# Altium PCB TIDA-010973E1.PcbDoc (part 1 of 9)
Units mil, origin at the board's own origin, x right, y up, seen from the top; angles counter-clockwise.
Board outline 5166 x 3669 mil, 8 copper layers (L01 - TOP, L02 - GND, L03 - SIG, L04 - GND, L05 - PWR, L06 - SIG, L07 - GND, L08 - BOTTOM), stack 61.7 mil thick; 677 components, 493 nets, 2522 pads, 1424 vias.
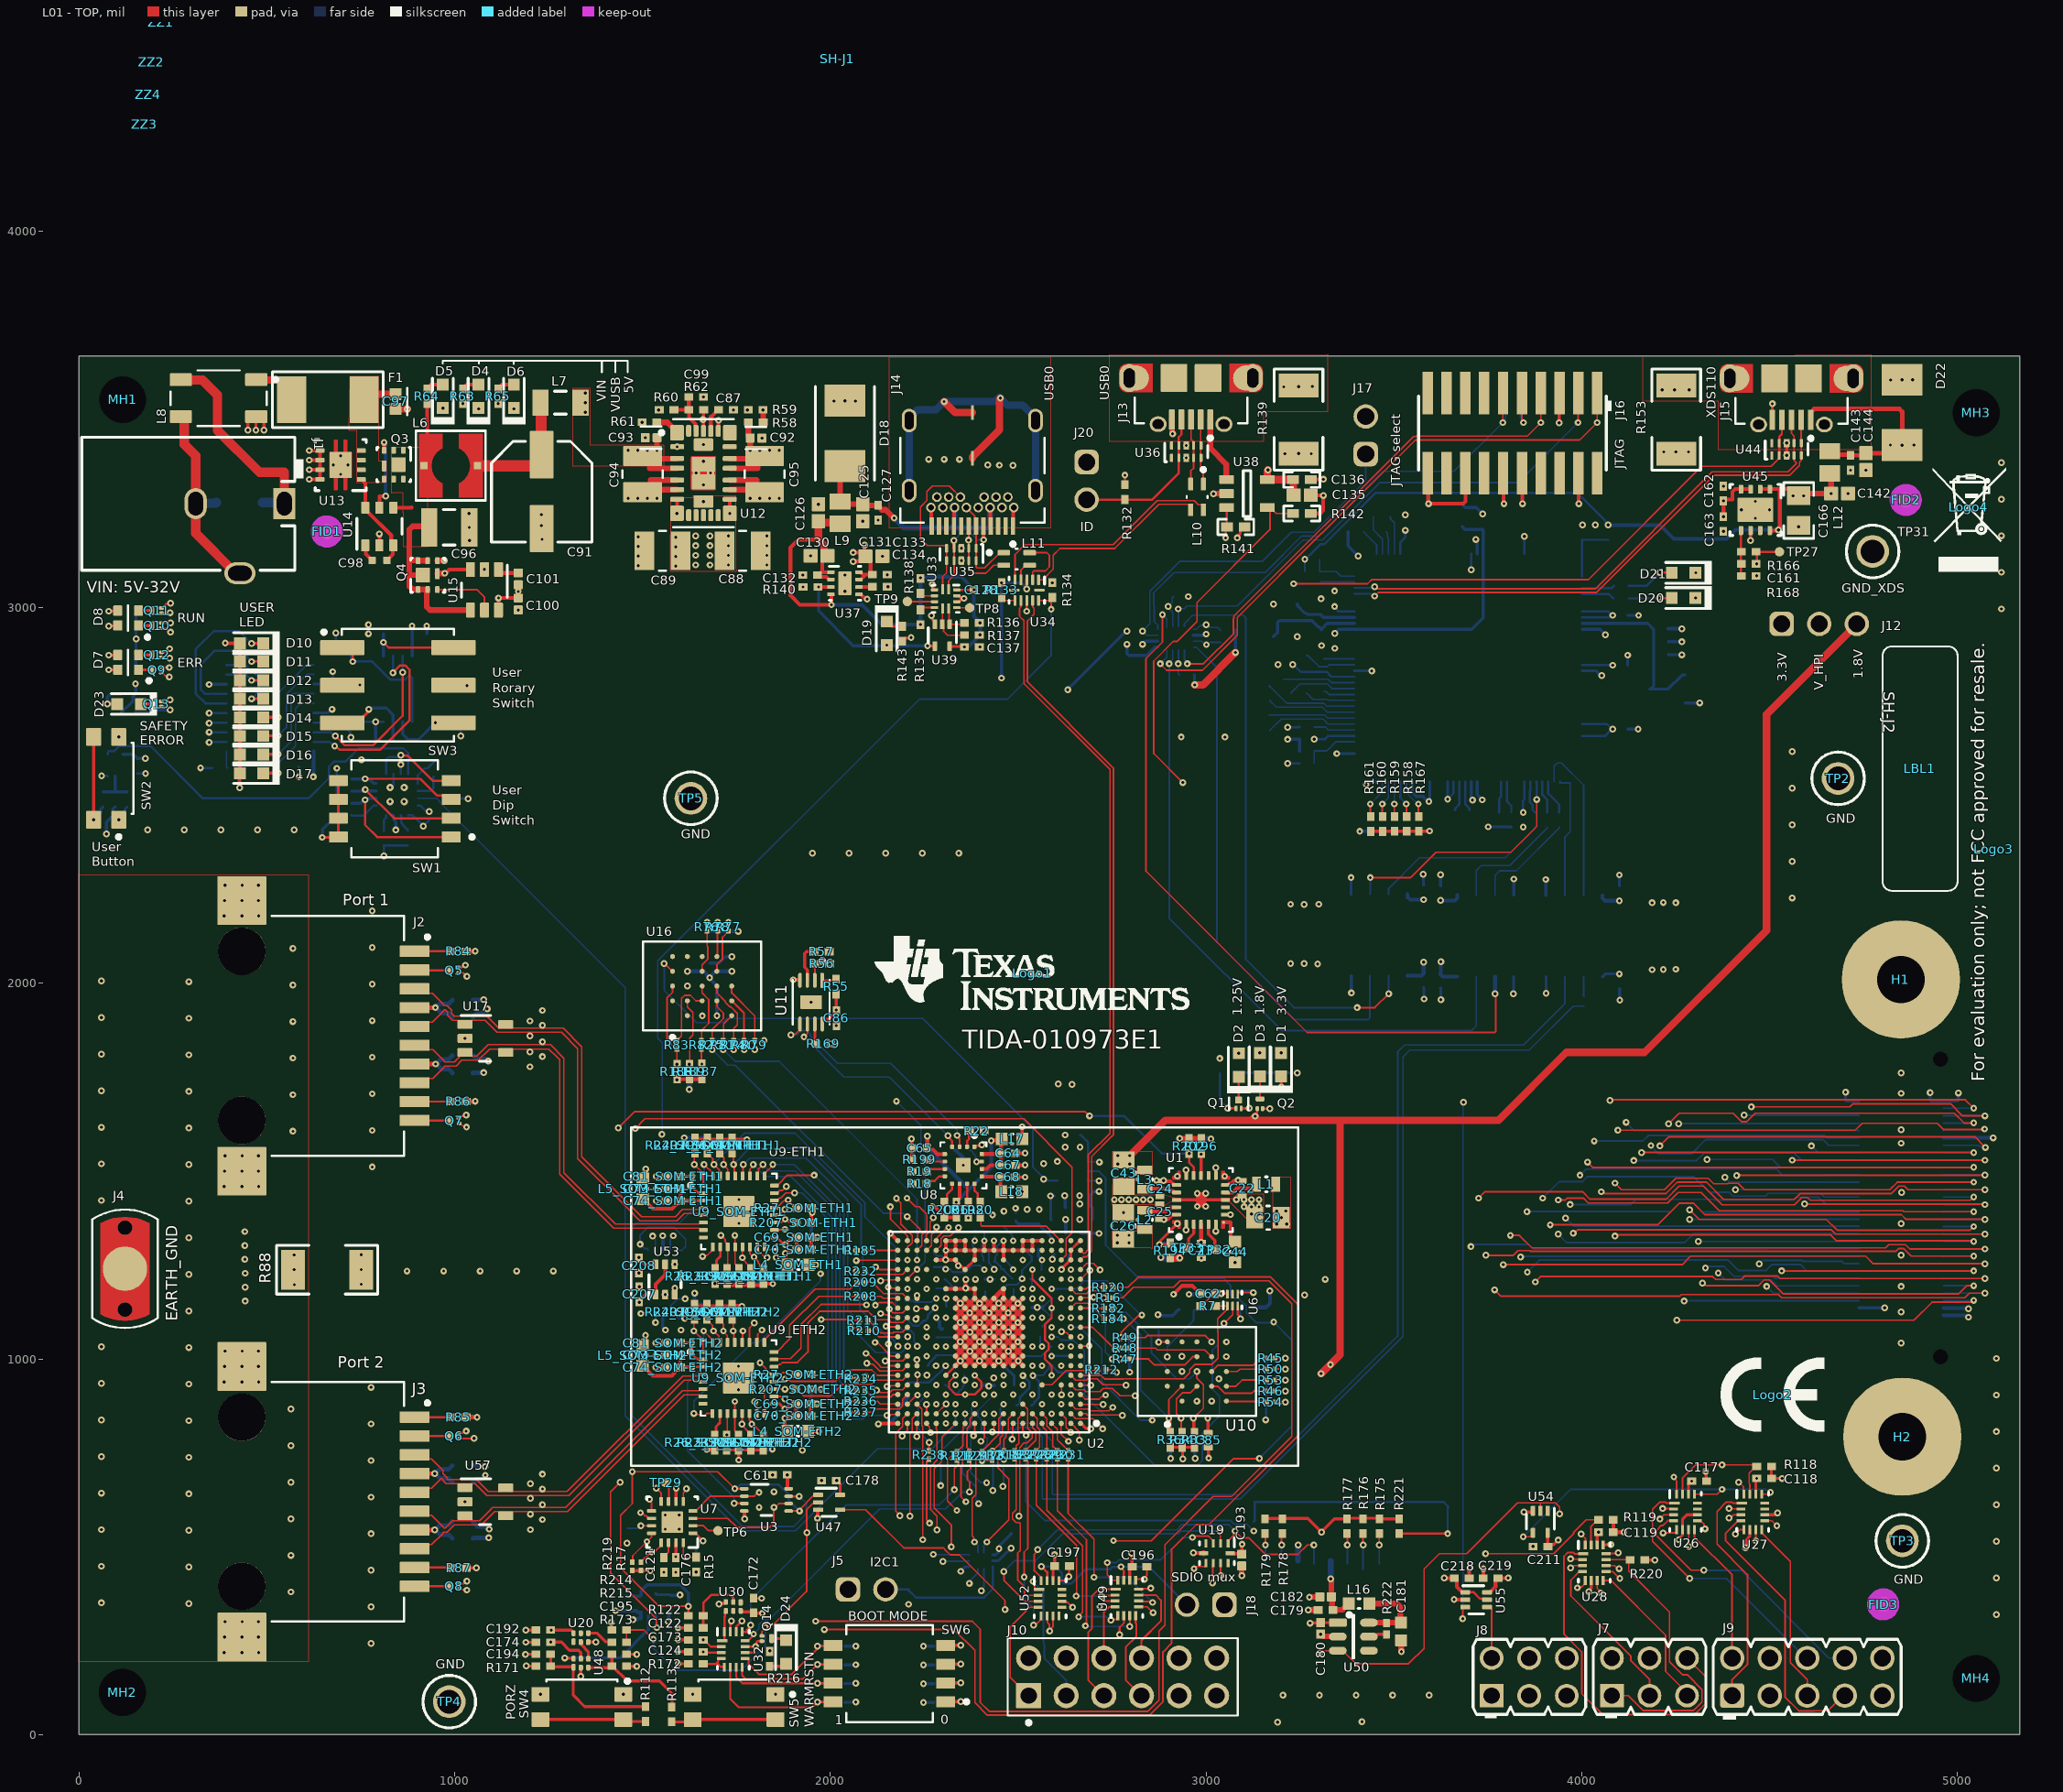
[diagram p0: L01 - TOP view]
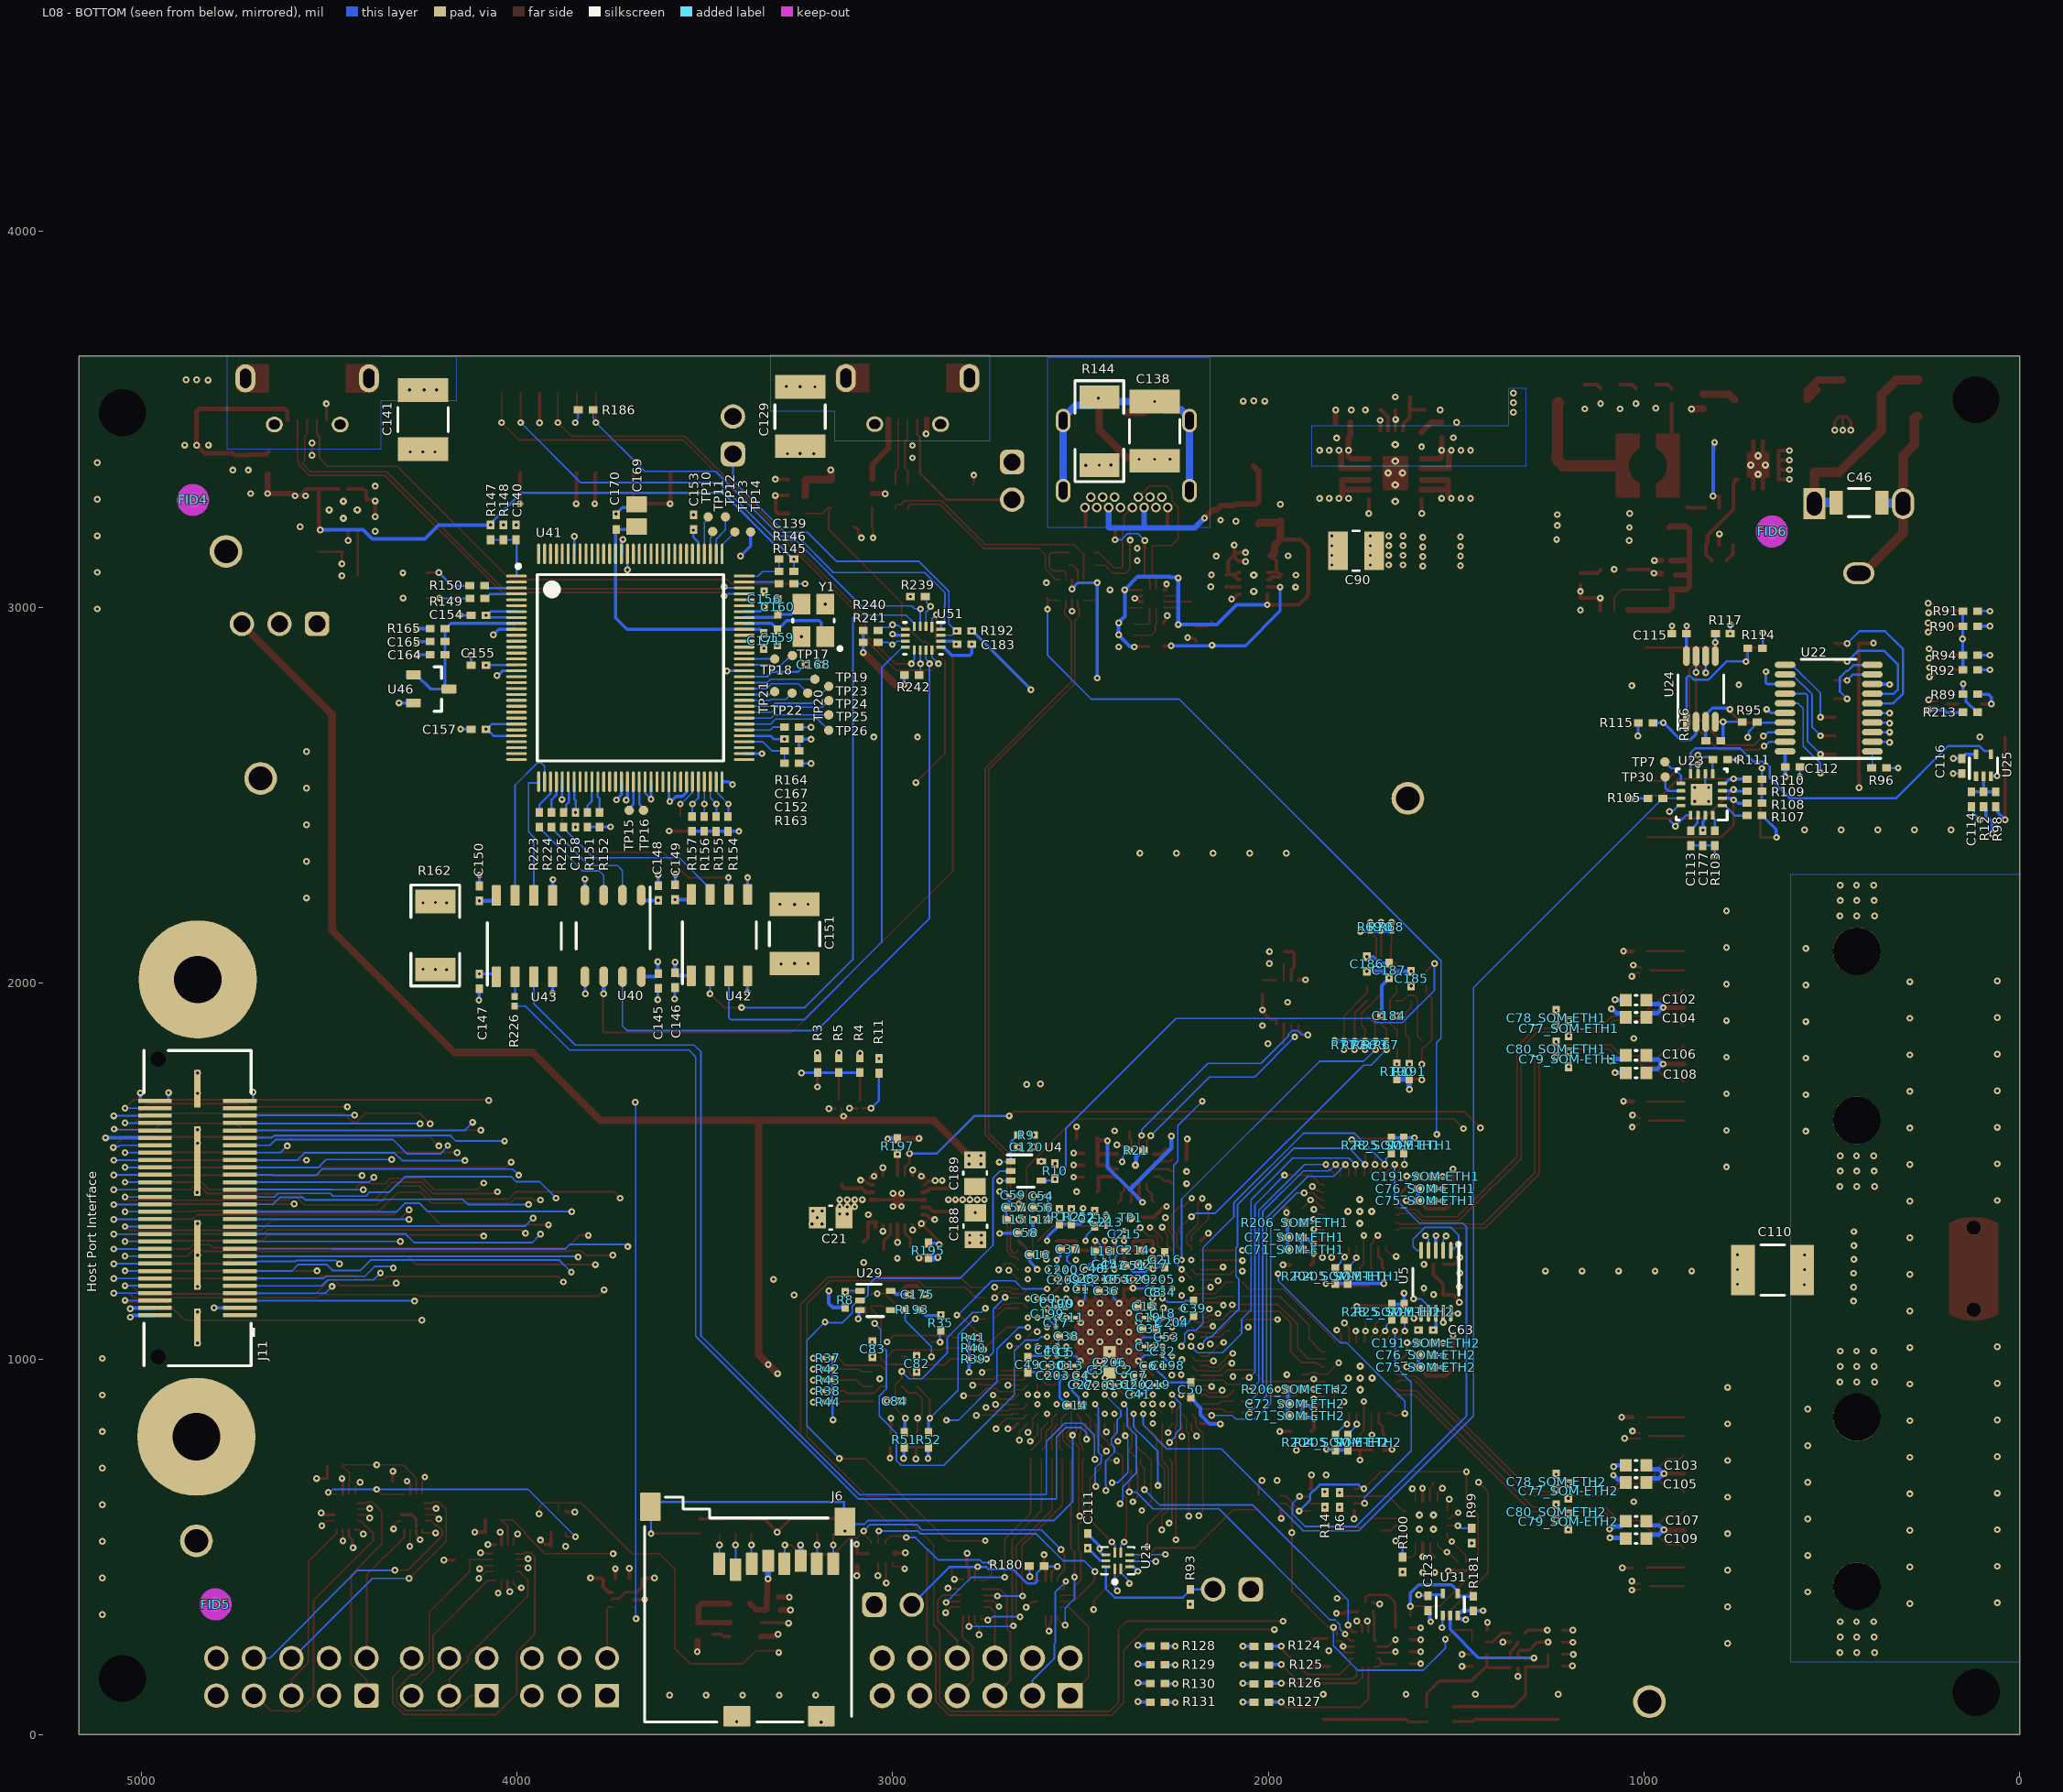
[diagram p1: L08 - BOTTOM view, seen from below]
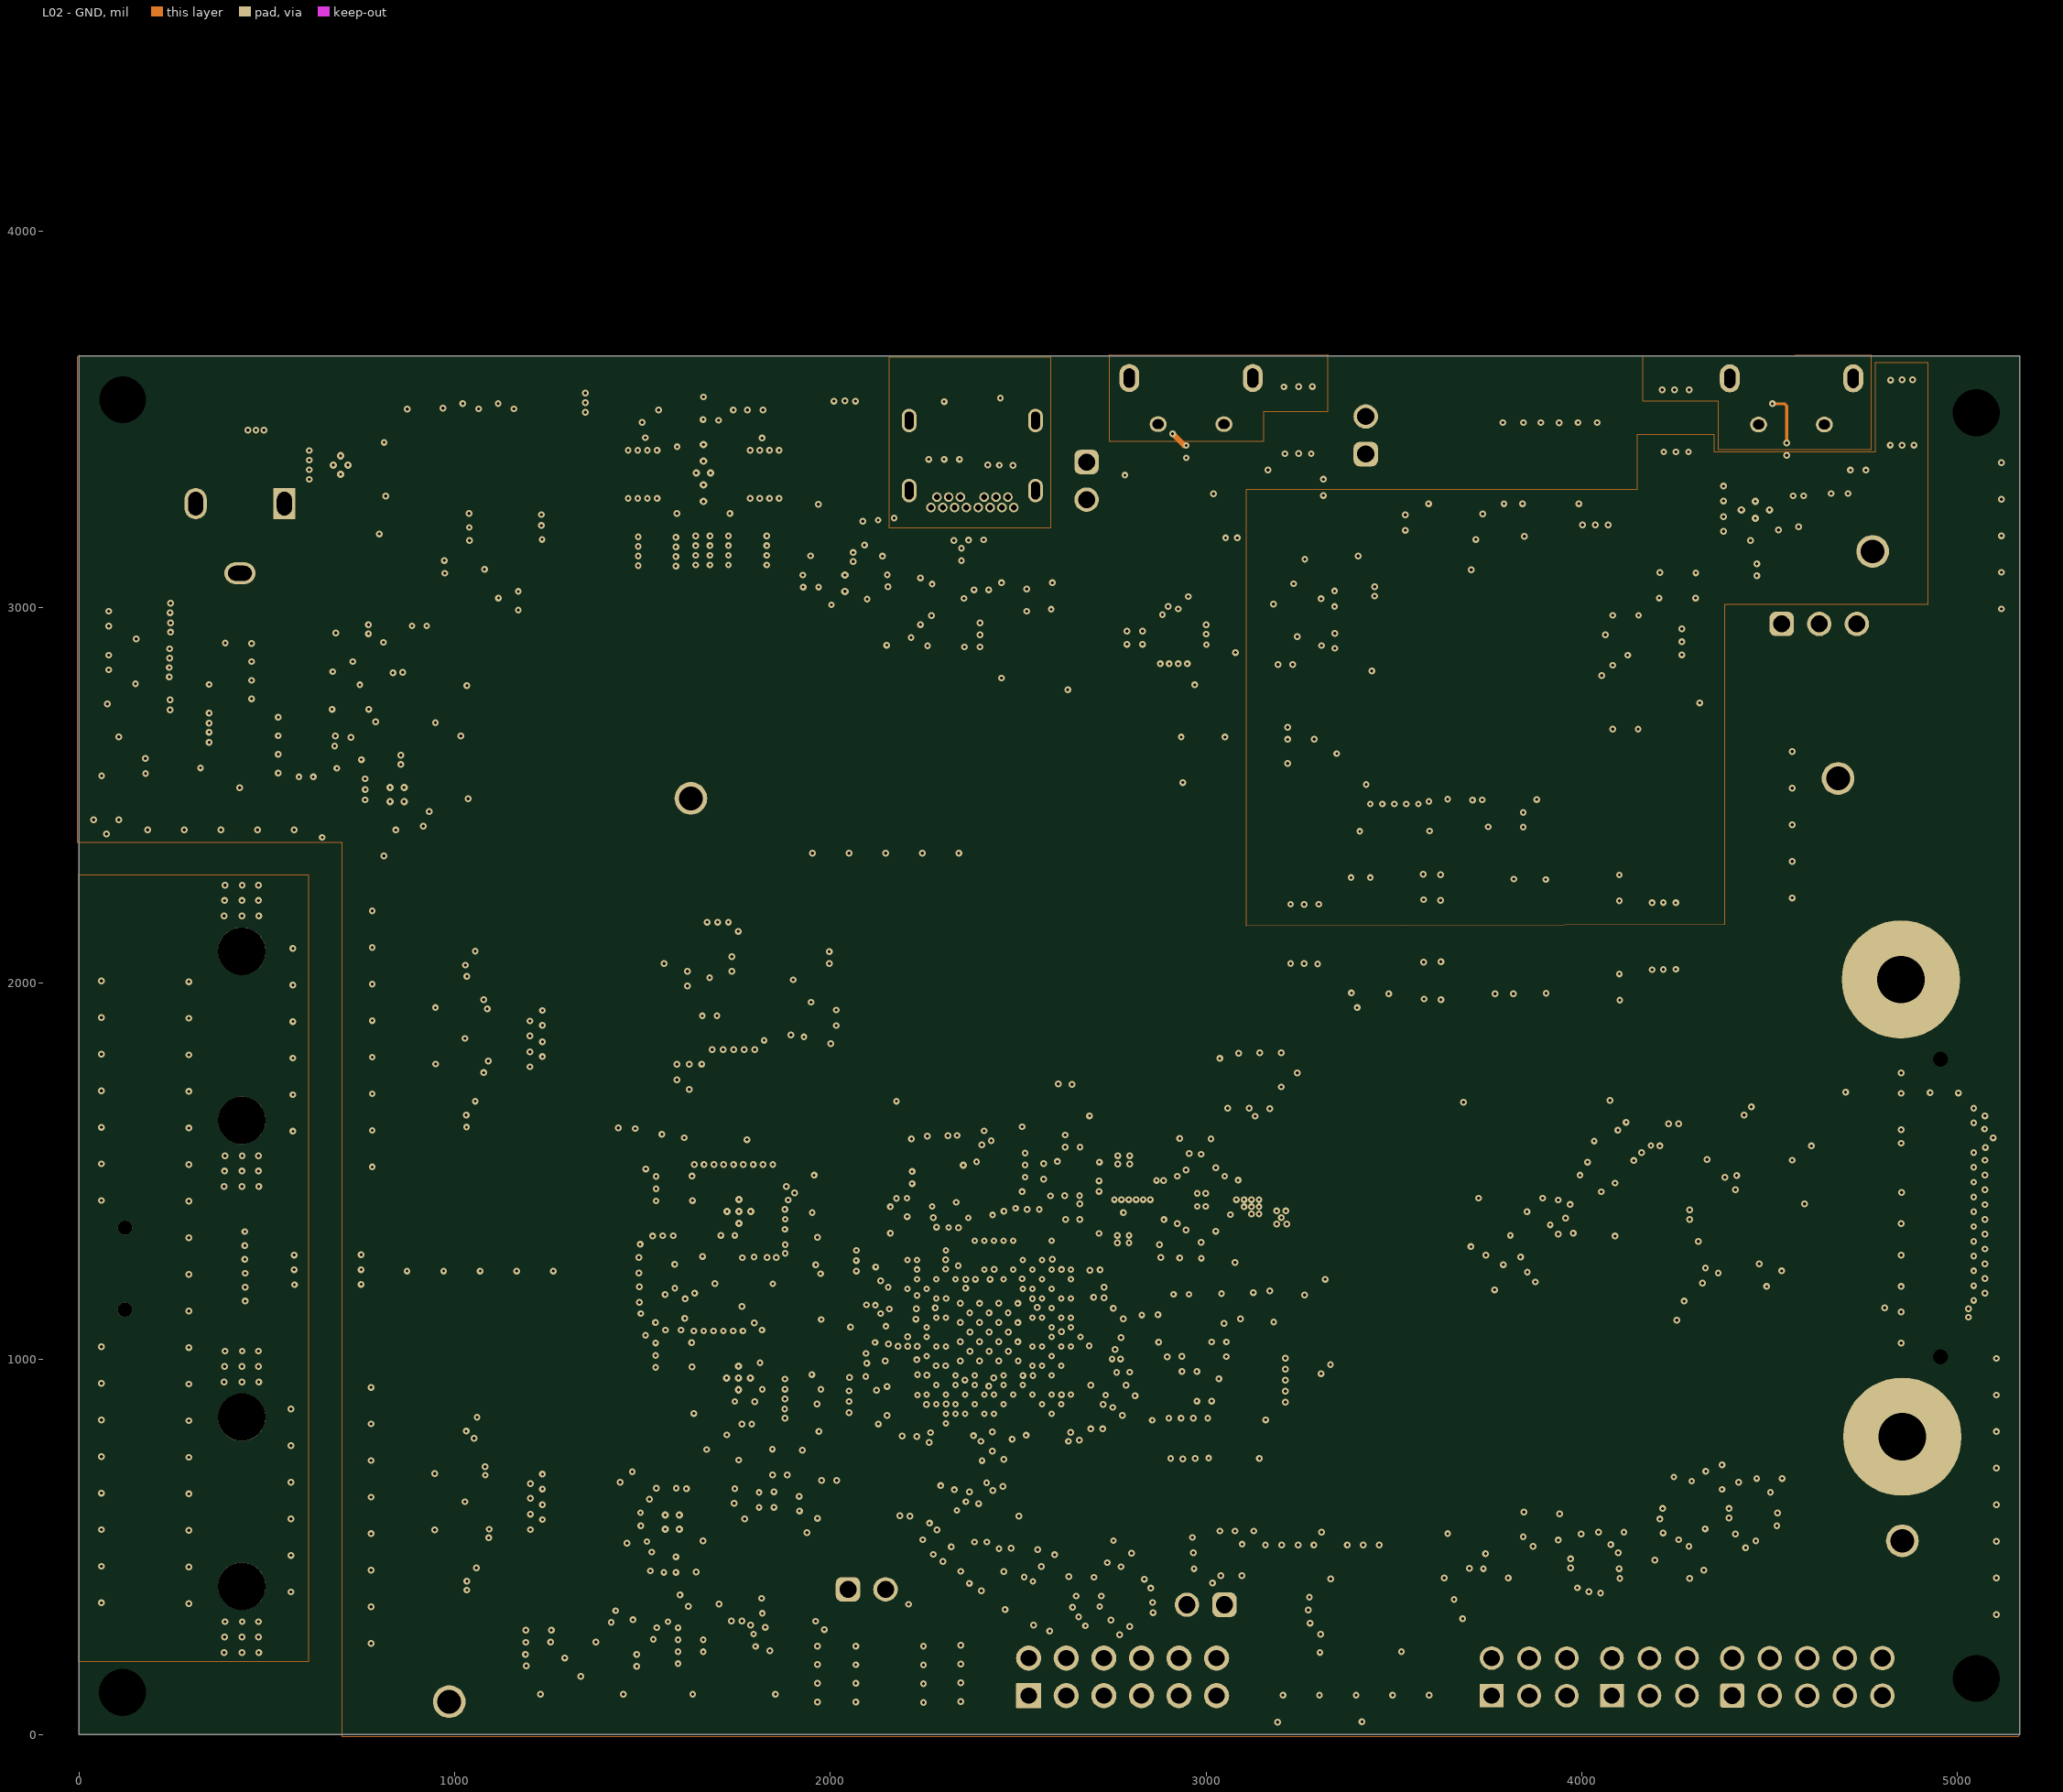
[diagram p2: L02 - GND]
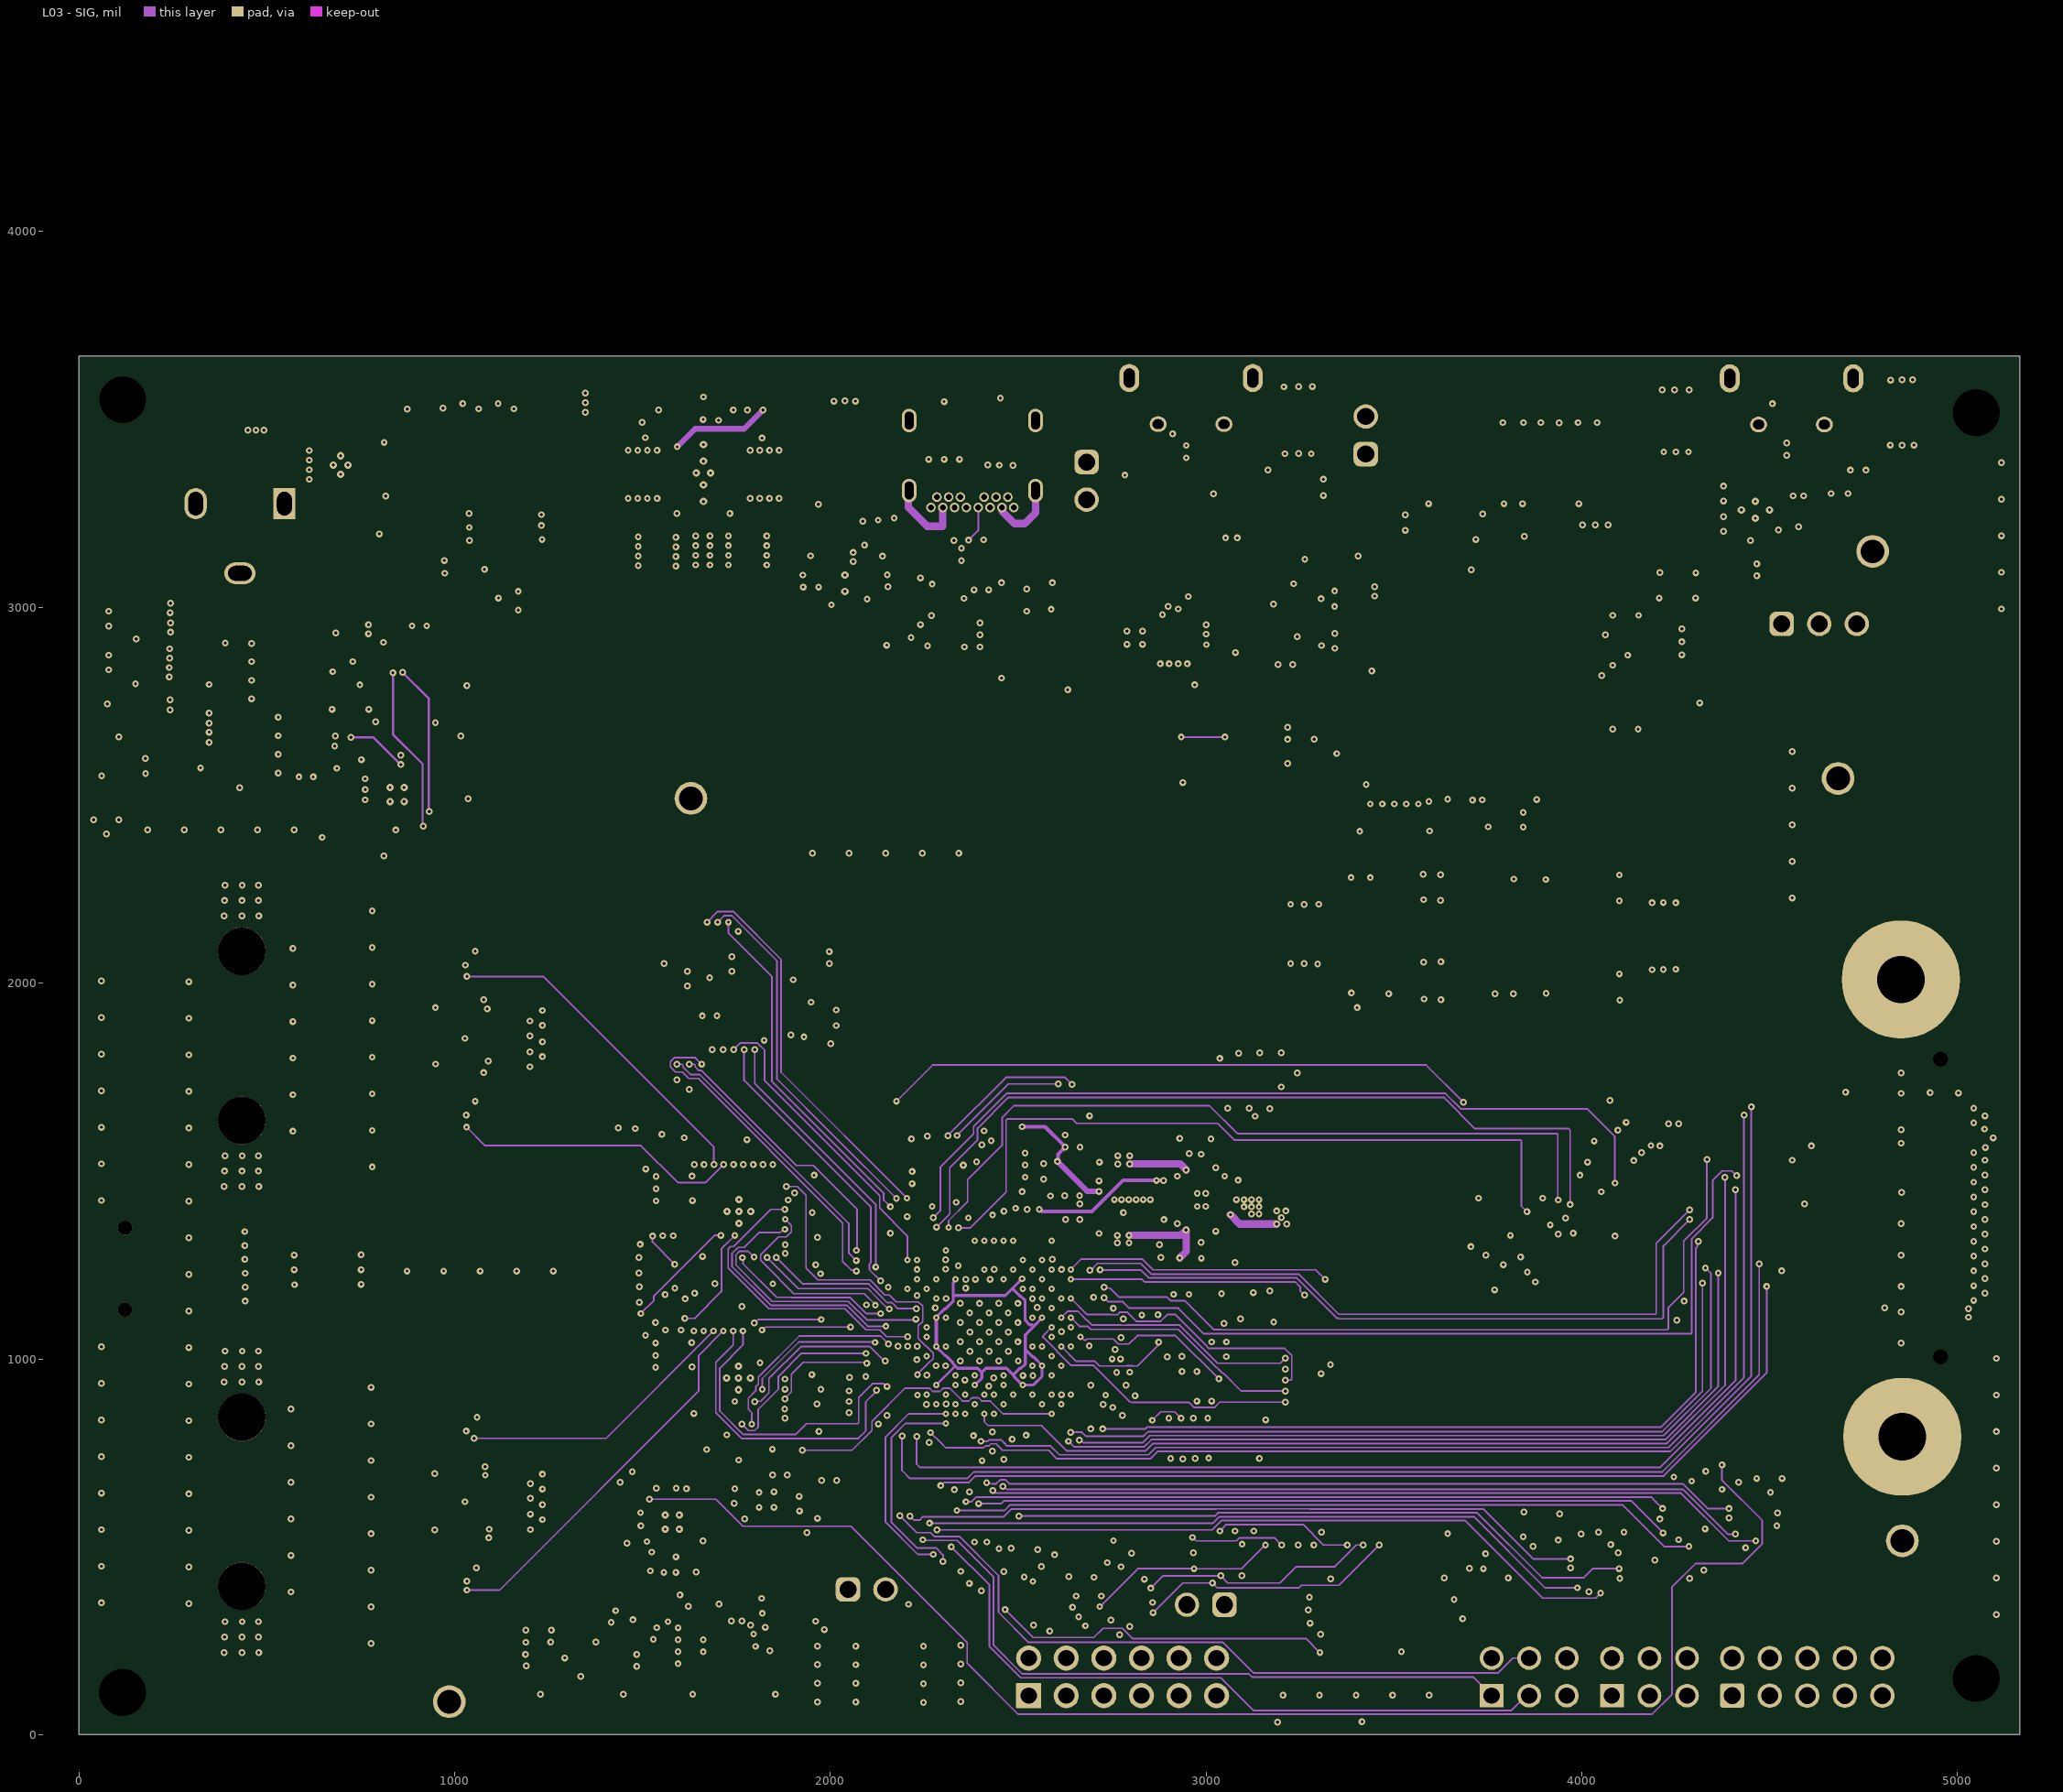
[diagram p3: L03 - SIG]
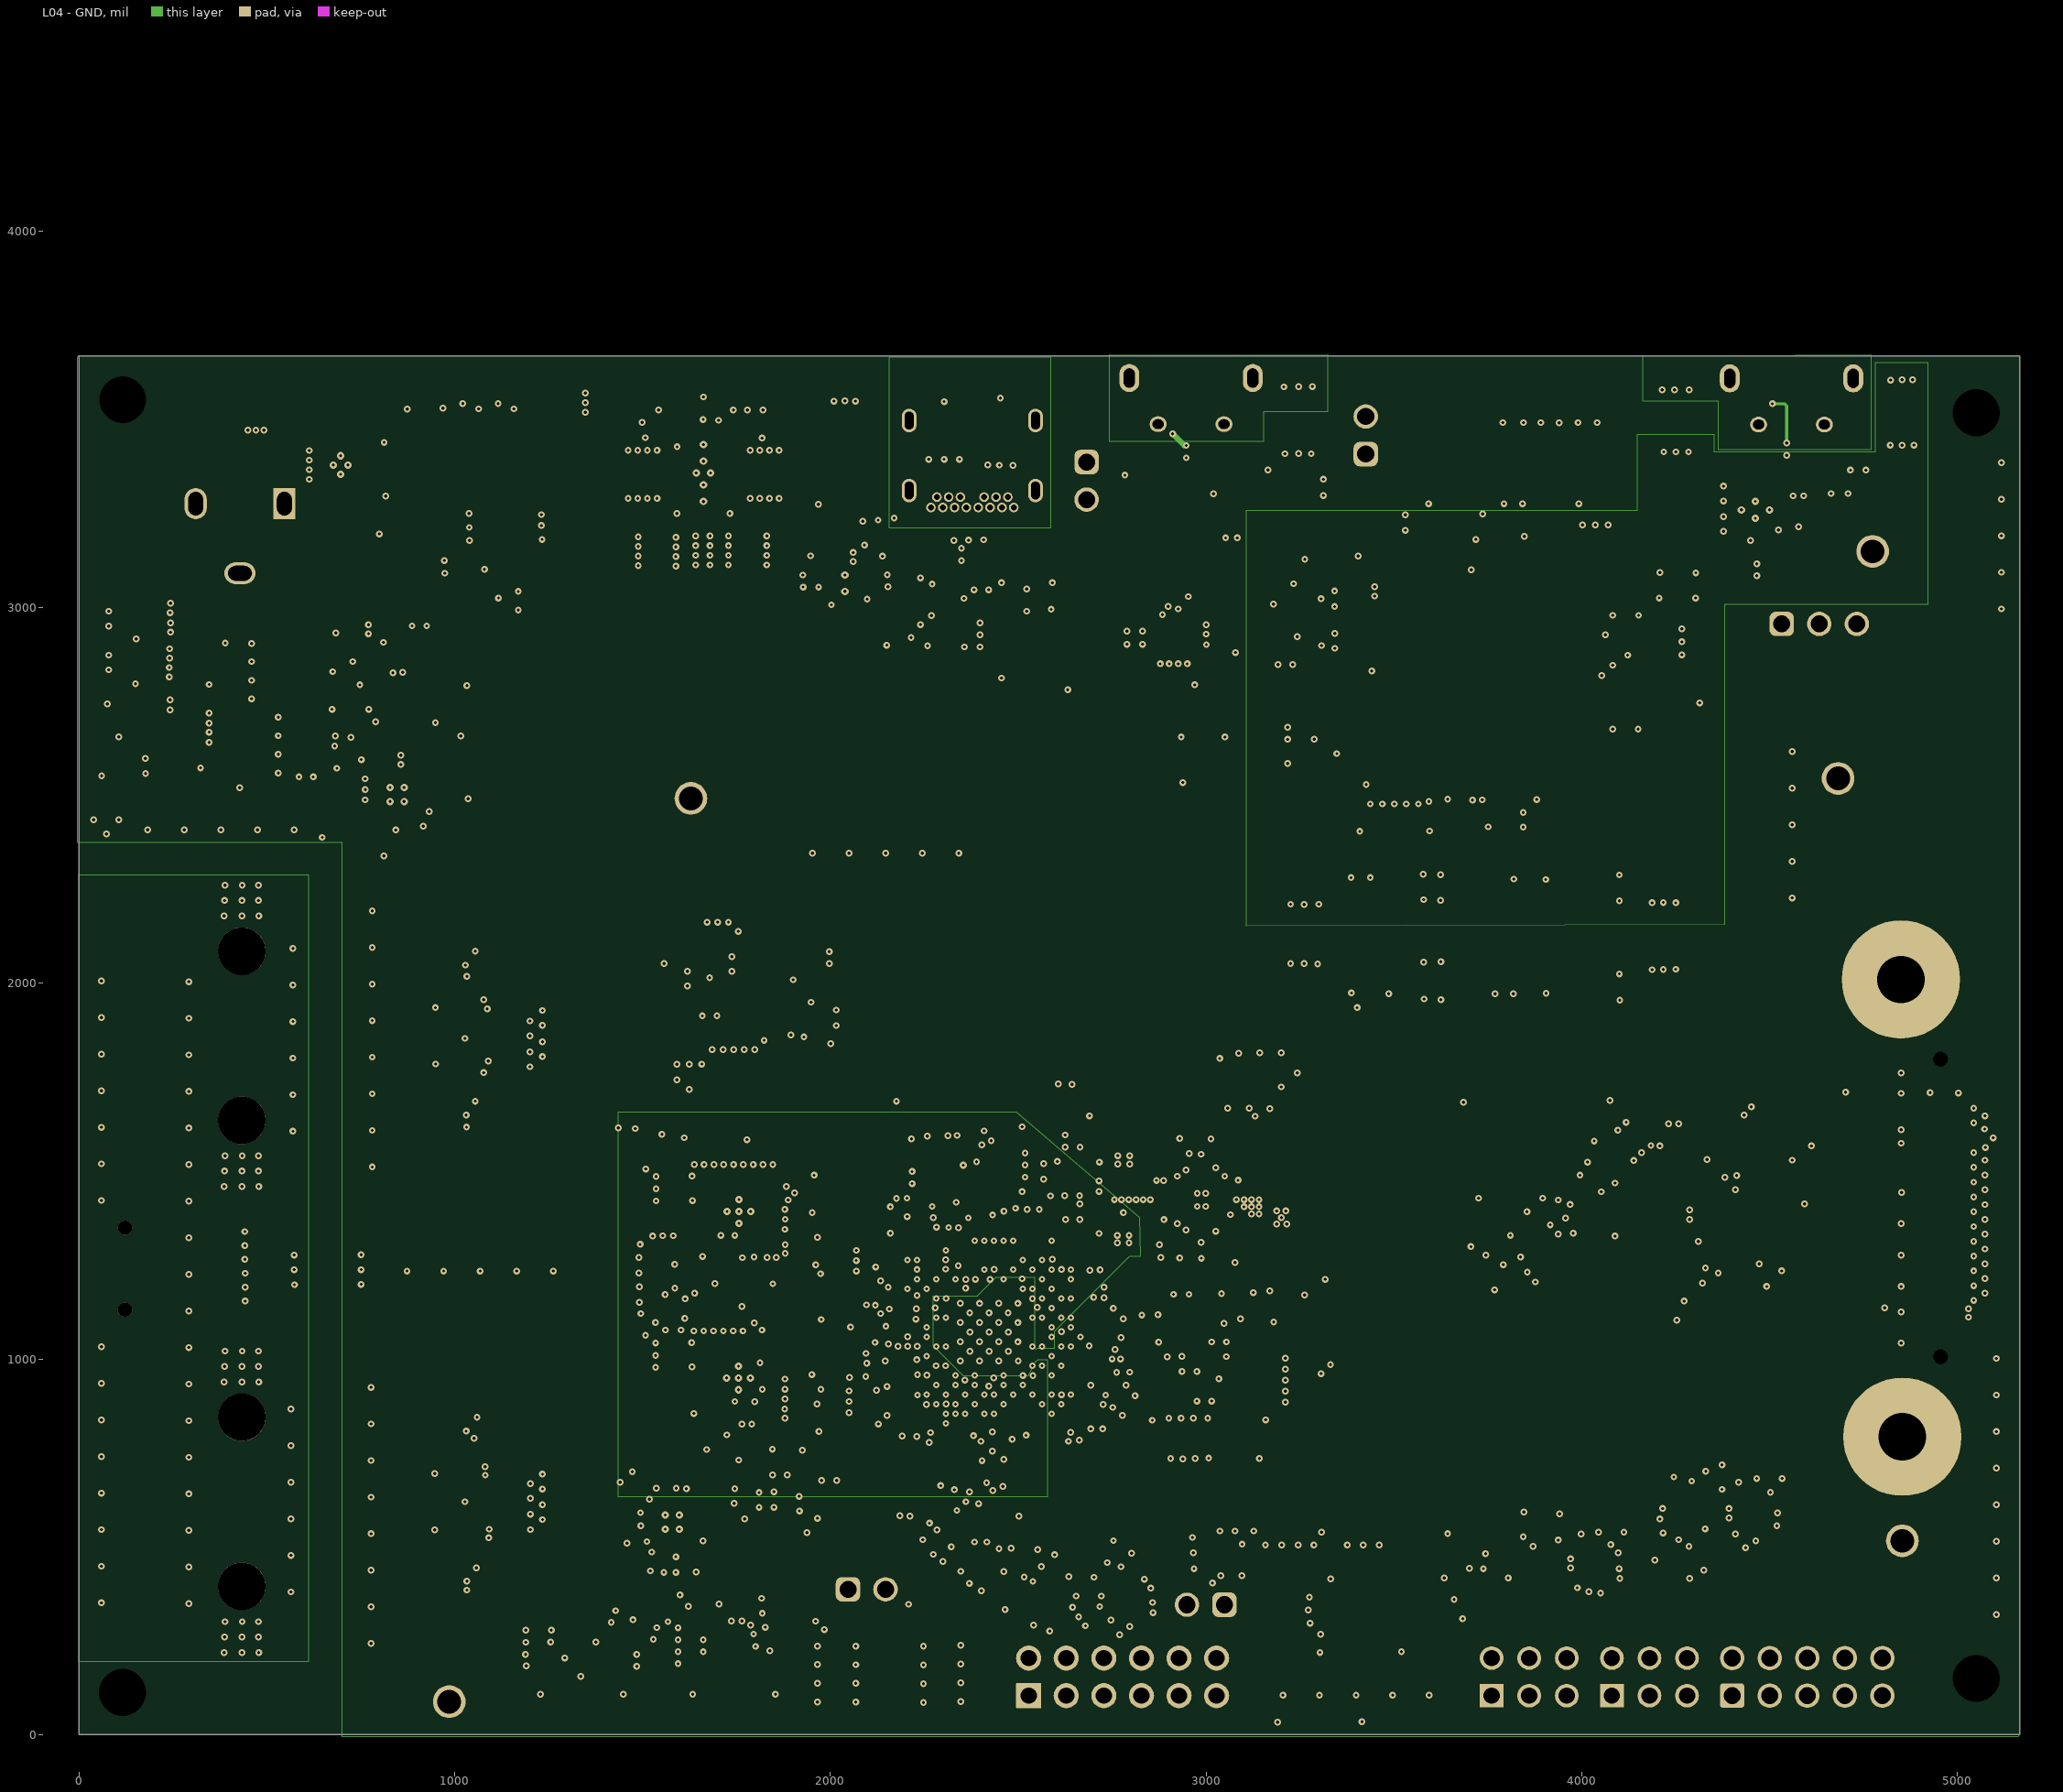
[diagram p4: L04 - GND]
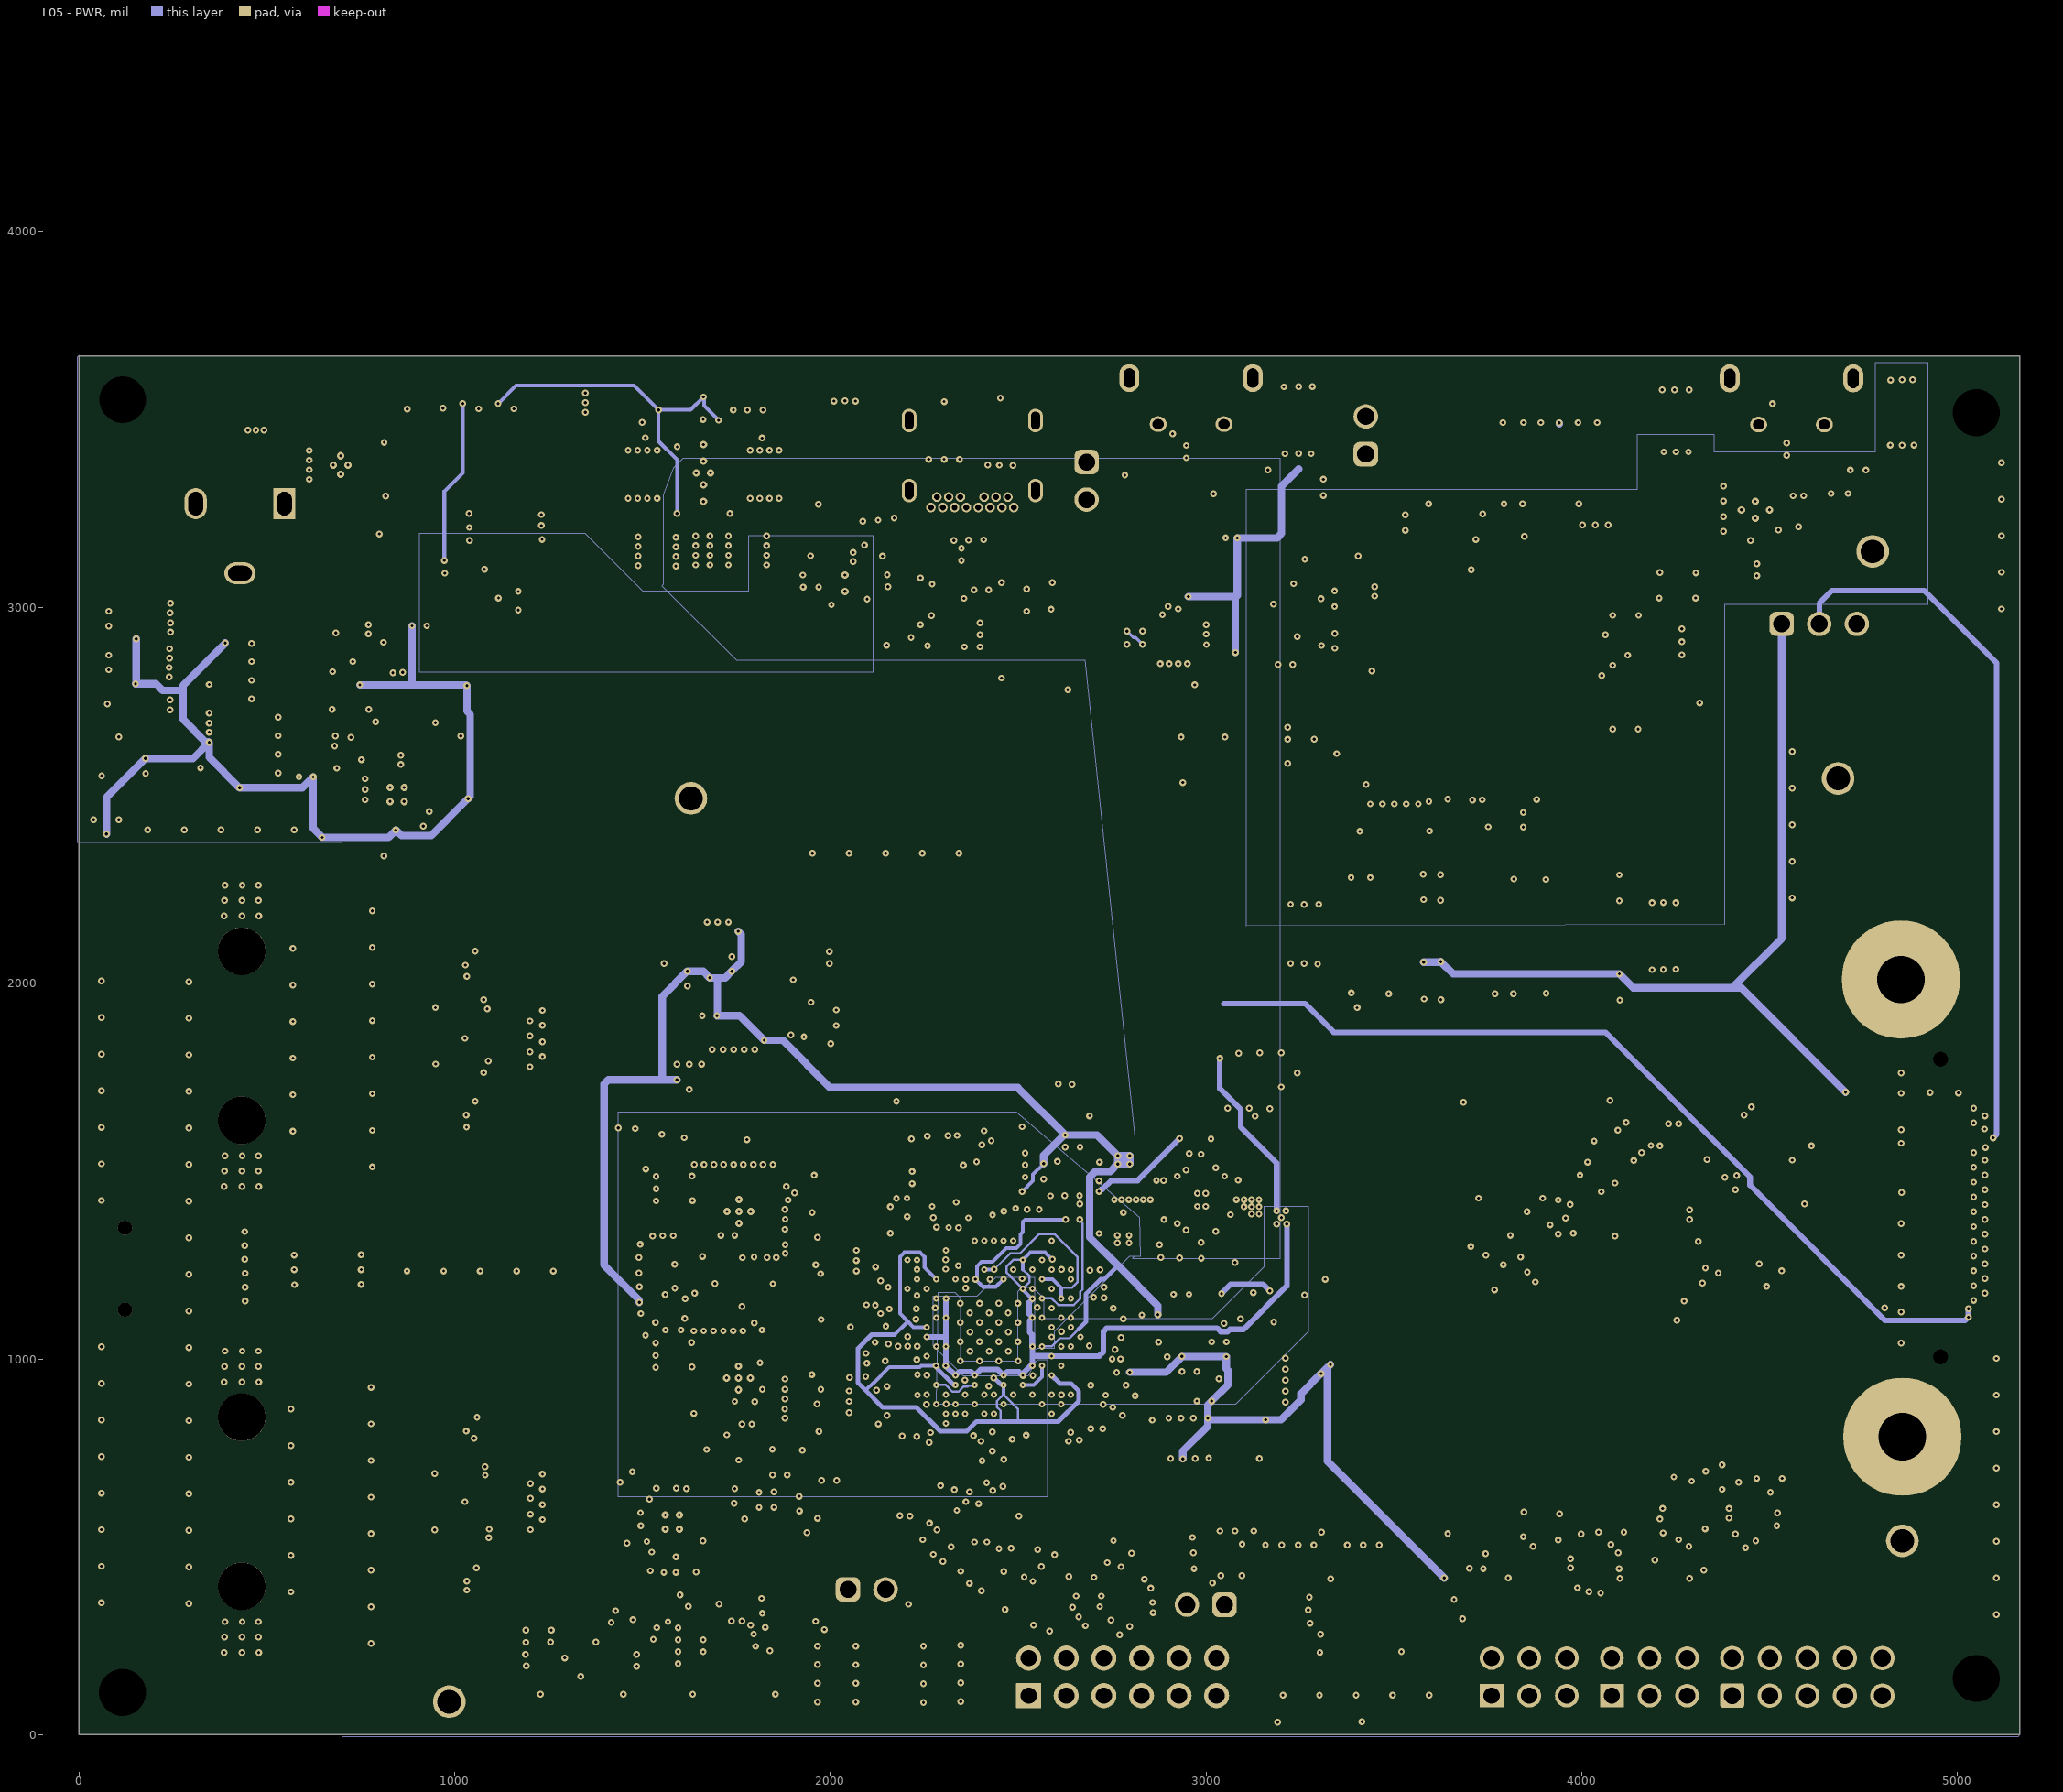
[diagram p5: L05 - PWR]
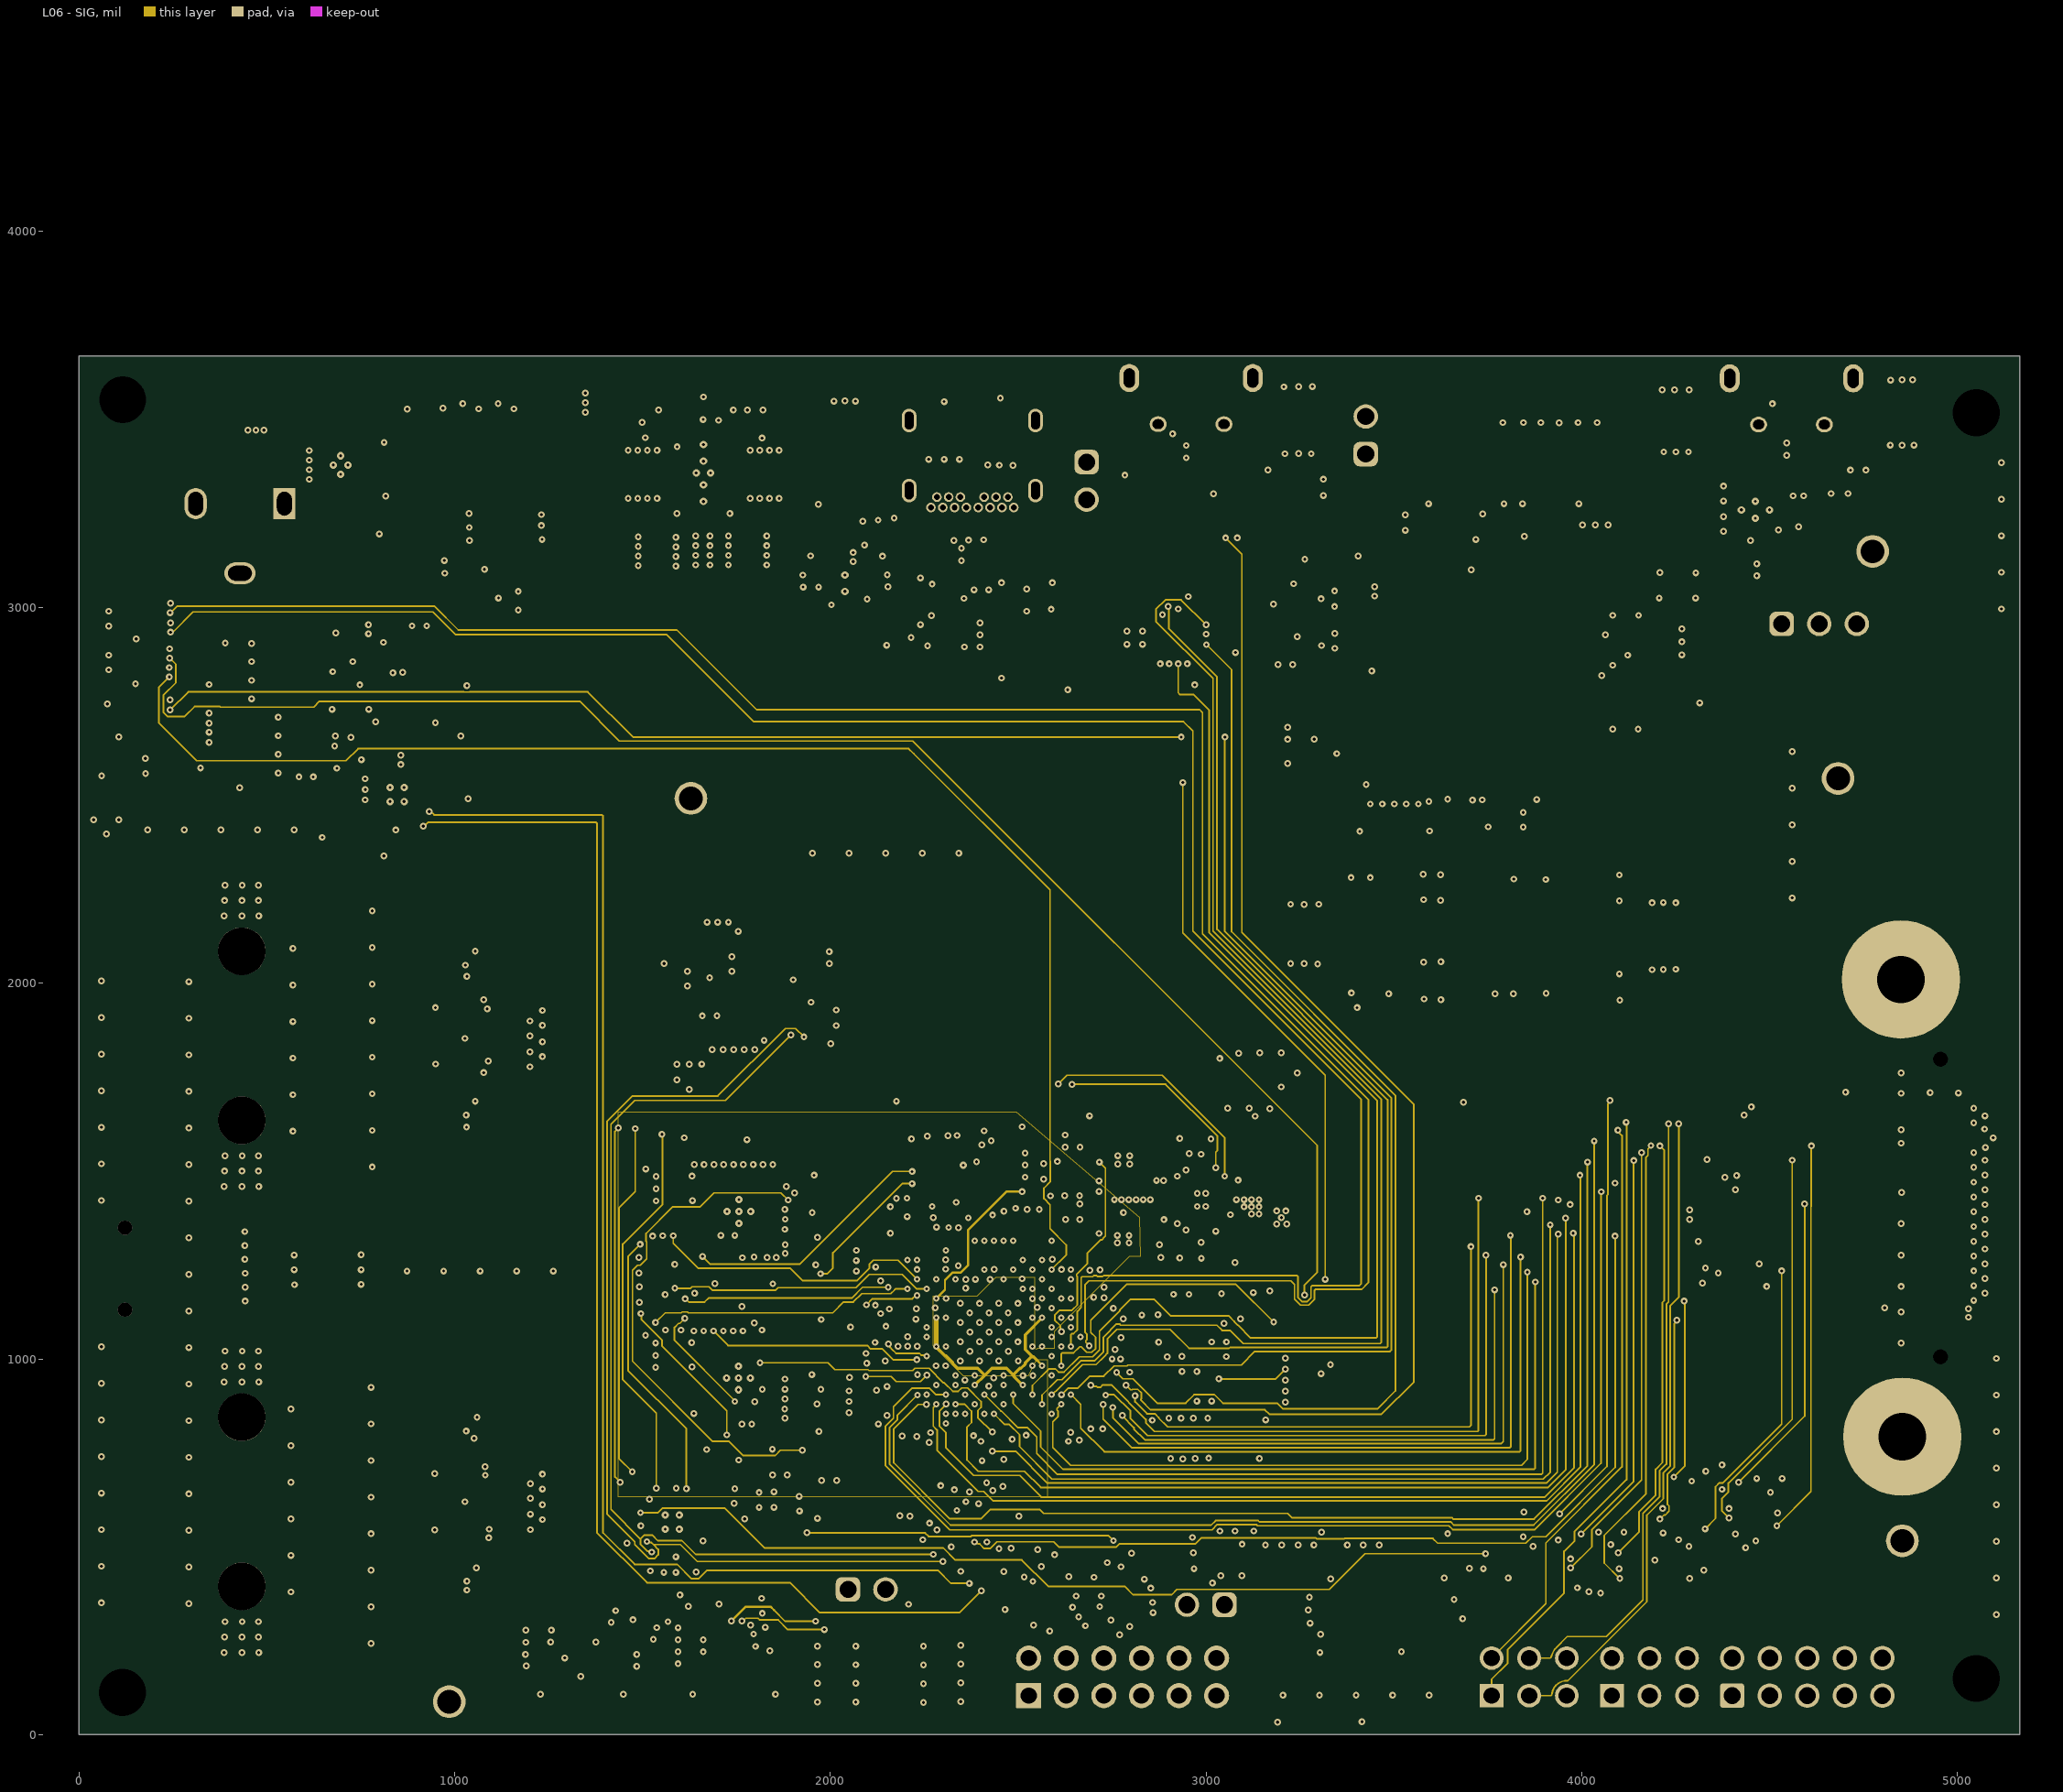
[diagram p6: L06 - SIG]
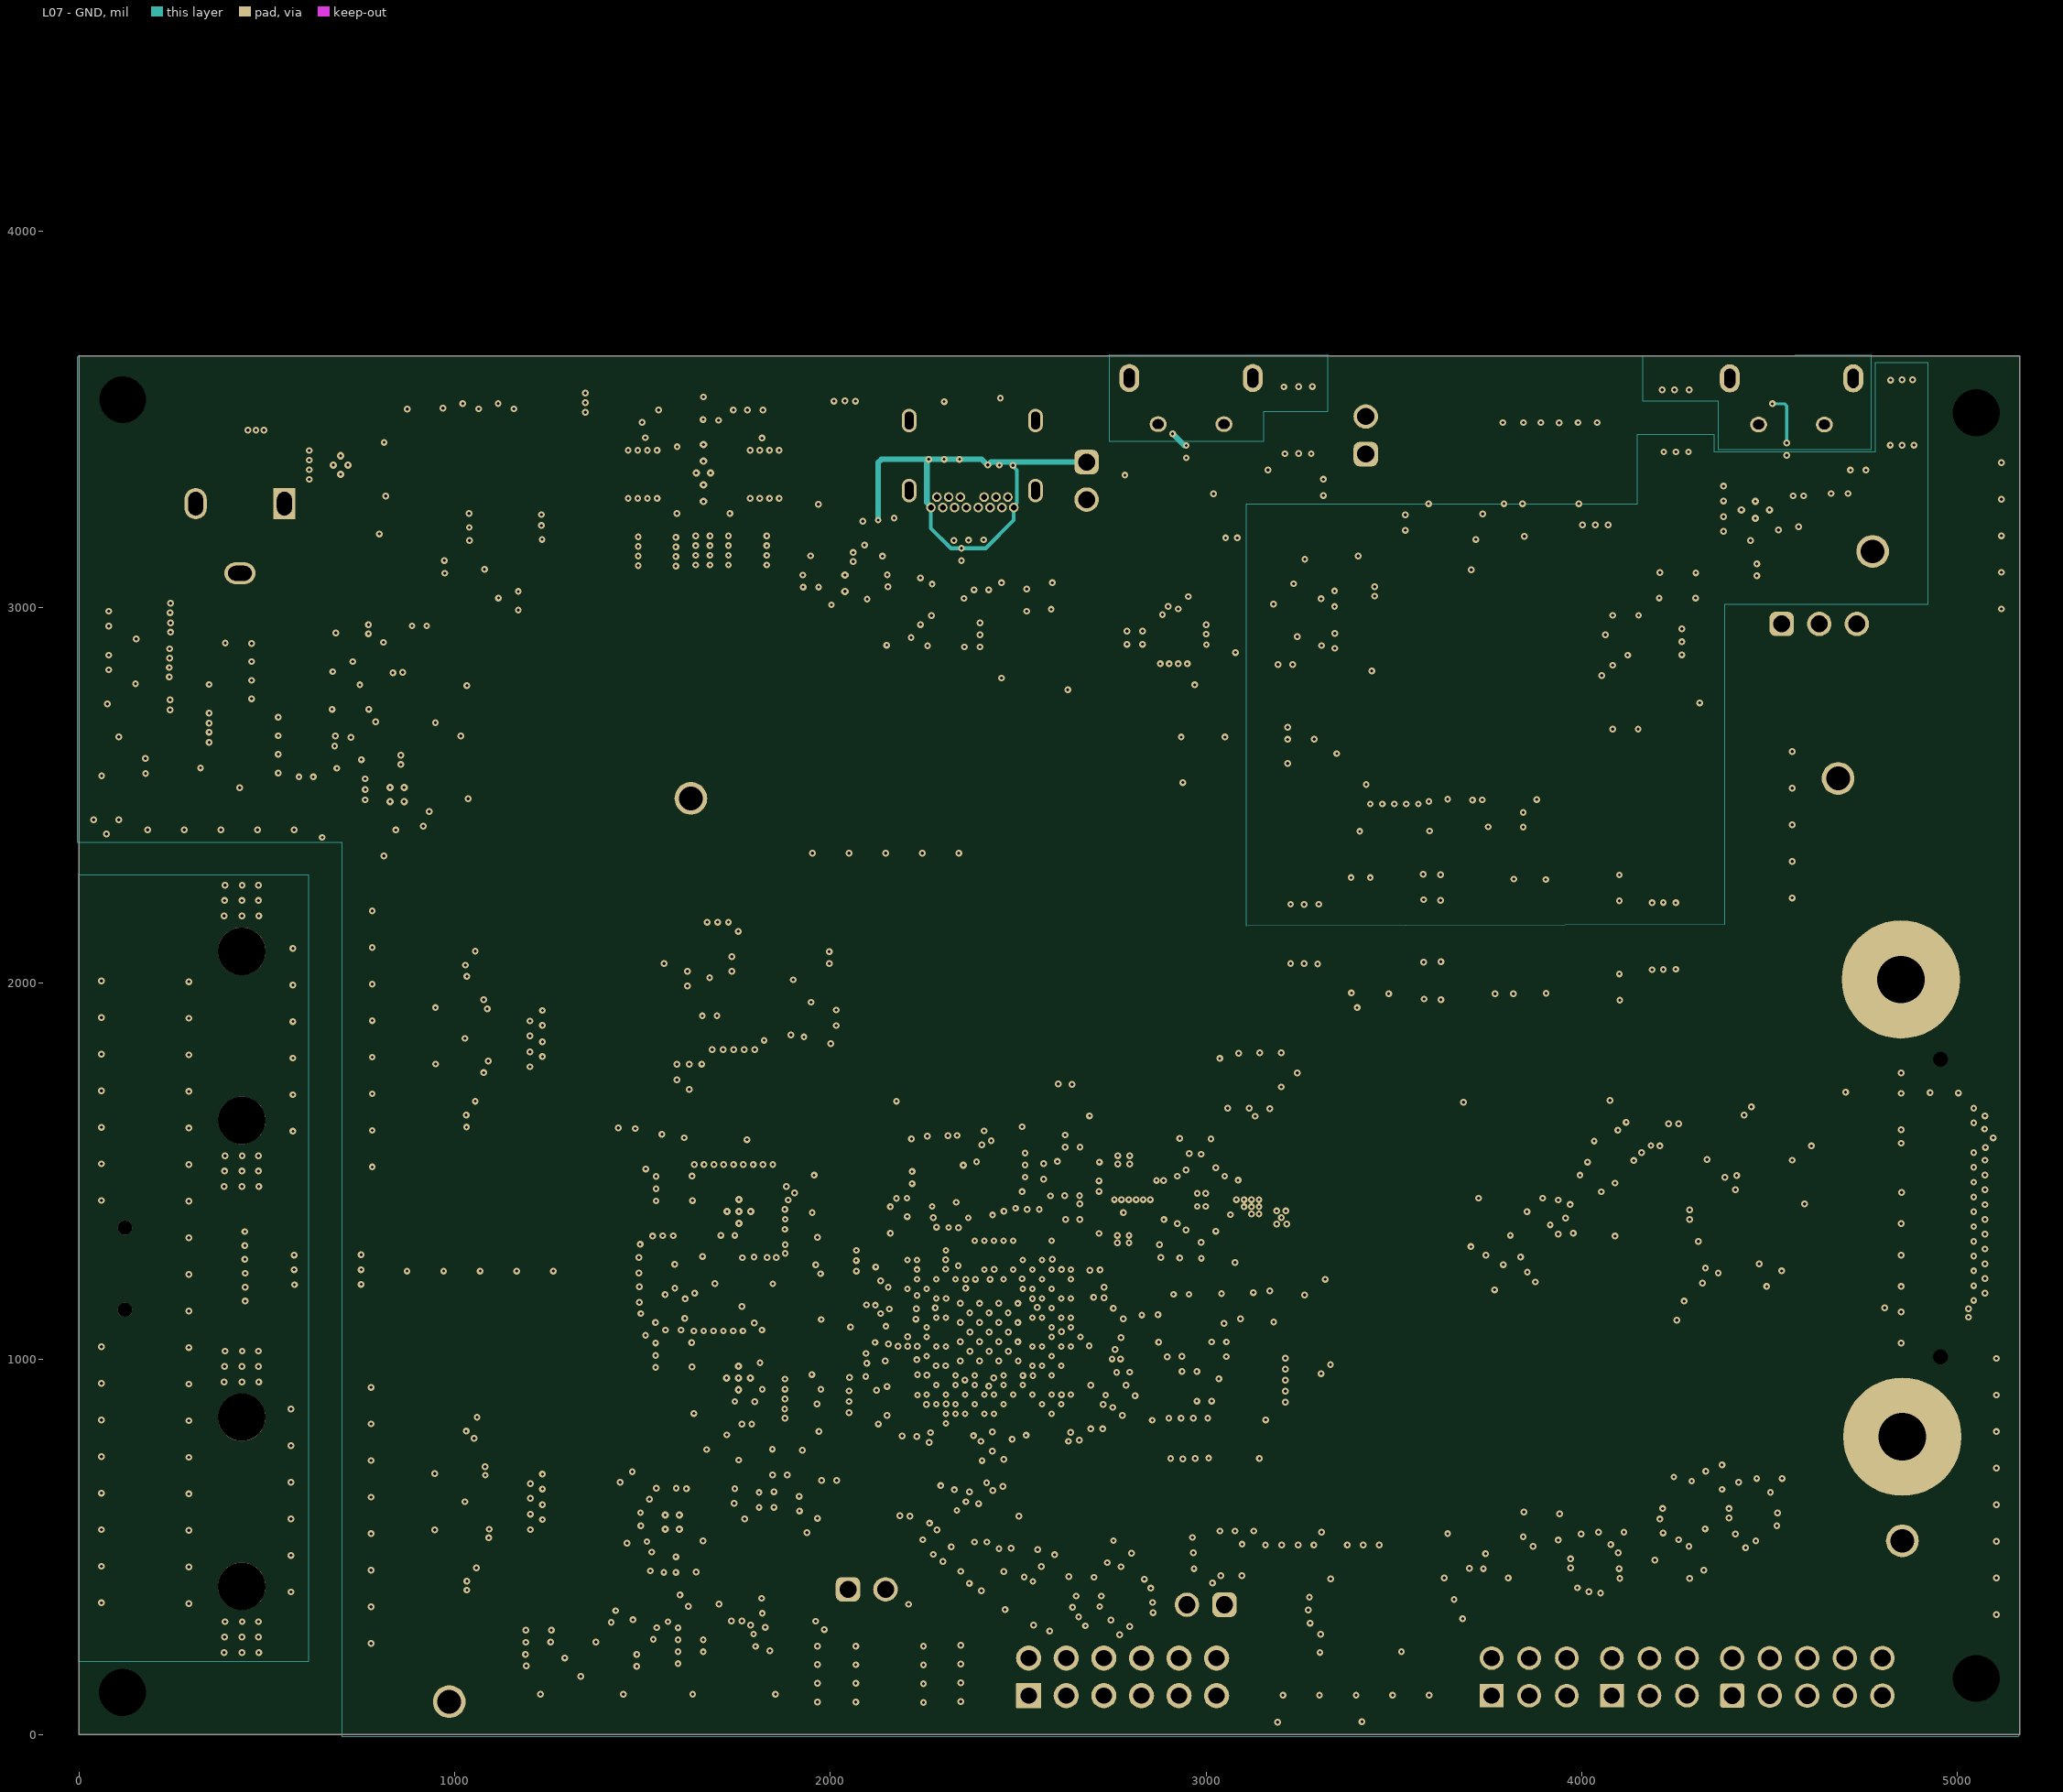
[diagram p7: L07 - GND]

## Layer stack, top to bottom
Top Solder: solder mask 0.4, Solder Resist, Dk 3.5
L01 - TOP: signal copper 1.8
Dielectric1: prepreg 2.75, 1080 RC64, Dk 4.2
L02 - GND: signal copper 1.2
Dielectric 2: core 3.5, 3.5mil Core, Dk 4.5
L03 - SIG: signal copper 0.6
Dielectric 3: prepreg 9.8, 1080 RC64 + 7628 RC43, Dk 4.1
L04 - GND: signal copper 1.2
Dielectric 4: core 20, 20mil Core, Dk 4.5
L05 - PWR: signal copper 1.2
Dielectric 5: prepreg 9.8, 1080 RC64 + 7628 RC43, Dk 4.1
L06 - SIG: signal copper 0.6
Dielectric 6: core 3.5, 3.5mil Core, Dk 4.5
L07 - GND: signal copper 1.2
Dielectric 7: prepreg 2.75, 1080 RC64, Dk 4.2
L08 - BOTTOM: signal copper 1.8
Bottom Solder: solder mask 0.4, Solder Resist, Dk 3.5

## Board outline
0,0 5166,0 5166,3669 0,3669

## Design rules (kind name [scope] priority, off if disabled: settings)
AcuteAngle [All] p1: isadvanced=TRUE minimum=4.50000000000000E+0001 checktracksonly=FALSE
AssemblyTestPointUsage [All] p1: isadvanced=TRUE valid=2
AssemblyTestpoint [All] p1: isadvanced=TRUE testpointundercomponent=TRUE minsize=40 maxsize=100 preferedsize=60 minholesize=0 maxholesize=40 preferedholesize=32 testpointgrid=1 usegrid=TRUE gridtolerance=0.01 allowsidetop=TRUE allowsidebottom=TRUE
BoardOutlineClearance BoardOutlineClearance_MountingHoles [OnCopper and InComponentClass('Mounting Holes')] p1: isadvanced=TRUE gap=39.37 ignorepadtopadclearanceinfootprint=FALSE
BoardOutlineClearance BoardOutlineClearance_Poly [OnCopper and IsPoly] p2: isadvanced=TRUE gap=25 ignorepadtopadclearanceinfootprint=FALSE
BoardOutlineClearance [OnCopper and Not InComponentClass('Logo') and not InComponentClass('FiducialMark') and not InRegion(1000,500,4000,800) and not InPoly] p3: isadvanced=TRUE gap=19.68 ignorepadtopadclearanceinfootprint=FALSE
Clearance Clearance_PE-to-others [InNet('EARTH_GND') vs All and not InNetClass('PE-side')] p1: gap=20 ignorepadtopadclearanceinfootprint=TRUE
Clearance Clearance_CLKs-to-others [InNetClass('CLK') vs All  and not (InNetClass('PWR') and IsTrack)] p2 off: gap=5.9 ignorepadtopadclearanceinfootprint=TRUE except(6: Arc-THPad Arc-Via Arc-Fill Arc-Poly Arc-Region Track-THPad Track-Via Track-Fill Track-Region SMDPad-Via THPad-Fill THPad-Poly THPad-Region; 7.87: SMDPad-SMDPad; 7.99: Track-SMDPad; 8: Arc-SMDPad; 10: Arc-Hole Track-Hole SMDPad-THPad SMDPad-Hole THPad-THPad THPad-Via Via-Hole Fill-Hole Poly-Hole Region-Hole; 14: Arc-Arc Arc-Track Track-Track; 20: Track-Poly THPad-Hole)
Clearance Clearance_DiffPairs-to-others [InAnyDifferentialPair vs All          and not InAnyDifferentialPair] p3: gap=5.9 ignorepadtopadclearanceinfootprint=TRUE except(6: Arc-THPad Arc-Via Arc-Fill Arc-Poly Arc-Region Track-THPad Track-Fill Track-Region SMDPad-Via THPad-Fill THPad-Poly THPad-Region; 8: Arc-SMDPad Track-SMDPad Track-Via SMDPad-SMDPad; 10: Arc-Hole Track-Track Track-Hole SMDPad-THPad SMDPad-Hole THPad-THPad THPad-Via Via-Hole Fill-Hole Poly-Hole Region-Hole; 14: Arc-Arc Arc-Track; 20: Track-Poly THPad-Hole)
Clearance Clearance_Keepouts [((IsTrack Or IsArc) And Not InPoly) And IsFree and IsKeepOut vs ((IsTrack Or IsArc) And Not InPoly) And IsFree and IsKeepOut] p4: gap=0 ignorepadtopadclearanceinfootprint=FALSE
Clearance Clearance_NTPHs [(ObjectKind = 'Pad') And (Layer = 'MultiLayer') And (PadIsPlated = 'False')] p5: gap=19.68 ignorepadtopadclearanceinfootprint=TRUE
Clearance Clearance_Poly [InPolygon] p6: gap=5.9 ignorepadtopadclearanceinfootprint=TRUE except(11.8: Poly-Poly)
Clearance SOC_POLY_4MIL [WithinRoom('SOC_POLY')] p7: gap=5.9 ignorepadtopadclearanceinfootprint=TRUE except(3.94: Track-SMDPad; 11.8: Poly-Poly)
Clearance Clearance_FiducialMark [IsKeepOut and InComponentClass('FiducialMark') vs IsPad and InComponentClass('FiducialMark')] p8: gap=0 ignorepadtopadclearanceinfootprint=FALSE
Clearance [All and not (HasFootprint('DQN0004A','DRL0006A')  or InAnyDifferentialPair)] p9: gap=5.9 ignorepadtopadclearanceinfootprint=TRUE except(5: Arc-Arc Arc-Track Arc-SMDPad Track-Track Track-SMDPad SMDPad-SMDPad; 10: Arc-Hole Track-Hole SMDPad-THPad SMDPad-Hole THPad-THPad THPad-Via Via-Hole Fill-Hole Poly-Hole Region-Hole; 20: THPad-Hole)
ComponentClearance ComponentClearance_j9J10 [InComponent('J9') or InComponent('J10')] p1: isadvanced=TRUE gap=0 collisioncheckmode=3 verticalgap=0 showdistances=FALSE
ComponentClearance ComponentClearance_L2L3 [InComponent('L2') or InComponent('L3')] p2: isadvanced=TRUE gap=0 collisioncheckmode=3 verticalgap=0 showdistances=FALSE
ComponentClearance ComponentClearance_L4L5L6 [InComponent('L4') or InComponent('L5') or InComponent('L6')] p3: isadvanced=TRUE gap=0 collisioncheckmode=3 verticalgap=0 showdistances=FALSE
ComponentClearance ComponentClearance_T1T2 [InComponent('T1') or InComponent('T2')] p4: isadvanced=TRUE gap=0 collisioncheckmode=3 verticalgap=0 showdistances=FALSE
ComponentClearance ComponentClearance_MountingHoles_FiducialMarks [InComponentClass('Mounting Holes') vs InComponentClass('FiducialMark')] p5: isadvanced=TRUE gap=50 collisioncheckmode=3 verticalgap=10 showdistances=FALSE
ComponentClearance ComponentClearance_Shunt [InComponentClass('Header') vs InComponentClass('Shunt')] p6: isadvanced=TRUE gap=0 collisioncheckmode=3 verticalgap=0 showdistances=FALSE
ComponentClearance ComponentClearance_Logo [InComponentClass('Logo')] p7: isadvanced=TRUE gap=30 collisioncheckmode=3 verticalgap=10 showdistances=FALSE
ComponentClearance ComponentClearance_ScrewToNut [(HasFootprint('NY PMS 440 0025 PH')) vs (HasFootprint('Keystone_1902C'))] p8: isadvanced=TRUE gap=5 collisioncheckmode=3 verticalgap=10 showdistances=FALSE
ComponentClearance ComponentClearance_MountingHoles [InComponentClass('Mounting Holes')] p9: isadvanced=TRUE gap=39.37 collisioncheckmode=3 verticalgap=100000 showdistances=FALSE
ComponentClearance ComponentClearance_SmallPassives [HasFootprint('0201*') or HasFootprint('0402*') or HasFootprint('0508') or HasFootprint('0603*') or HasFootprint('0612') or HasFootprint('0805*') or HasFootprint('0815*') or HasFootprint('0830*') or HasFootprint('1206*') or HasFootprint('1210*') or HasFootprint('1808*') or HasFootprint('1812*') or HasFootprint('1825*') or HasFootprint('2010*') or HasFootprint('2220*') or HasFootprint('2225*') or HasFootprint('2512*') or HasFootprint('2728*') or HasFootprint('3518*') vs HasFootprint('0201*') or HasFootprint('0402*') or HasFootprint('0508') or HasFootprint('0603*') or HasFootprint('0612') or HasFootprint('0805*') or HasFootprint('0815*') or HasFootprint('0830*') or HasFootprint('1206*') or HasFootprint('1210*') or HasFootprint('1808*') or HasFootprint('1812*') or HasFootprint('1825*') or HasFootprint('2010*') or HasFootprint('2220*') or HasFootprint('2225*') or HasFootprint('2512*') or HasFootprint('2728*') or HasFootprint('3518*')] p10: isadvanced=TRUE gap=7.87 collisioncheckmode=3 verticalgap=10 showdistances=FALSE
ComponentClearance ComponentClearance_THtoSMT [IsThruComponent vs IsSMTComponent] p11: isadvanced=TRUE gap=30 collisioncheckmode=3 verticalgap=30 showdistances=FALSE
ComponentClearance ComponentClearance_THtoTH [IsThruComponent vs IsThruComponent] p12: isadvanced=TRUE gap=20 collisioncheckmode=3 verticalgap=30 showdistances=FALSE
ComponentClearance [All] p13: isadvanced=TRUE gap=11.81 collisioncheckmode=3 verticalgap=10 showdistances=FALSE
DiffPairsRouting [All] p1 off: maxlimit=10 minlimit=10 mostfreqgap=10 toplayer_minwidth=15 toplayer_maxwidth=15 toplayer_prefwidth=15 midlayer1_minwidth=15 midlayer1_maxwidth=15 midlayer1_prefwidth=15 midlayer2_minwidth=15 midlayer2_maxwidth=15 midlayer2_prefwidth=15 midlayer3_minwidth=15 midlayer3_maxwidth=15 midlayer3_prefwidth=15 midlayer4_minwidth=15 midlayer4_maxwidth=15 midlayer4_prefwidth=15 midlayer5_minwidth=15 midlayer5_maxwidth=15 midlayer5_prefwidth=15 midlayer6_minwidth=15 midlayer6_maxwidth=15 midlayer6_prefwidth=15 bottomlayer_minwidth=15 bottomlayer_maxwidth=15 bottomlayer_prefwidth=15 maxuncoupledlength=500
DiffPairsRouting DiffPairsRouting_100 [InDifferentialPair('ETH1_TD') Or InDifferentialPair('ETH1_RD') Or InDifferentialPair('ETH0_TD') Or InDifferentialPair('ETH0_RD')] p2: maxlimit=10 minlimit=6 mostfreqgap=10 toplayer_mingap=7.6 toplayer_maxgap=7.6 toplayer_prefgap=7.6 toplayer_minwidth=3.5 toplayer_maxwidth=3.5 toplayer_prefwidth=3.5 midlayer1_maxgap=6 midlayer1_prefgap=6 midlayer1_minwidth=3.5 midlayer1_maxwidth=3.5 midlayer1_prefwidth=3.5 midlayer5_maxgap=6 midlayer5_prefgap=6 midlayer5_minwidth=3.5 midlayer5_maxwidth=3.5 midlayer5_prefwidth=3.5 bottomlayer_mingap=7.6 bottomlayer_maxgap=7.6 bottomlayer_prefgap=7.6 bottomlayer_minwidth=3.5 bottomlayer_maxwidth=3.5 bottomlayer_prefwidth=3.5 impedanceprofiledriven=TRUE impedanceprofileid={D992D10A-1EBD-42F0-896D-96F15BEDB385} impedanceprofilevalue=100.000000 maxuncoupledlength=500
DiffPairsRouting DiffPairsRouting_85 [InDifferentialPair('XDSET_1_D') Or InDifferentialPair('AM261_USB0_D')] p3: maxlimit=10 minlimit=4.6 mostfreqgap=10 toplayer_mingap=4.8 toplayer_maxgap=4.8 toplayer_prefgap=4.8 toplayer_minwidth=4.5 toplayer_maxwidth=4.5 toplayer_prefwidth=4.5 midlayer1_maxgap=4.6 midlayer1_prefgap=4.6 midlayer1_minwidth=4.6 midlayer1_maxwidth=4.6 midlayer1_prefwidth=4.6 midlayer5_maxgap=4.6 midlayer5_prefgap=4.6 midlayer5_minwidth=4.6 midlayer5_maxwidth=4.6 midlayer5_prefwidth=4.6 bottomlayer_mingap=4.8 bottomlayer_maxgap=4.8 bottomlayer_prefgap=4.8 bottomlayer_minwidth=4.5 bottomlayer_maxwidth=4.5 bottomlayer_prefwidth=4.5 impedanceprofiledriven=TRUE impedanceprofileid={57D57B9A-E69A-4B53-BB80-8C6D088C861B} impedanceprofilevalue=85.000000 maxuncoupledlength=500
FabricationTestPointUsage TestPointUsage [All] p1: isadvanced=TRUE valid=2 allowmultiple=FALSE
FabricationTestpoint Testpoint [All] p1: isadvanced=TRUE side=3 testpointundercomponent=TRUE minsize=40 maxsize=100 preferedsize=60 minholesize=0 maxholesize=40 preferedholesize=32 testpointgrid=1 allowsidetop=TRUE allowsidebottom=TRUE usegrid=TRUE gridtolerance=0.01
FanoutControl Fanout_LCC [IsLCC] p1: isadvanced=TRUE bgadir=Out bgaviamode=Centered fanoutstyle=Auto fanoutdirection=Alternating viagrid=1 // Fanout_LCC (Default Rule)
FanoutControl Fanout_BGA [IsBGA] p2: isadvanced=TRUE bgadir=Out bgaviamode=Centered fanoutstyle=Auto fanoutdirection=Alternating viagrid=1 // Fanout_BGA (Default Rule)
FanoutControl Fanout_SOIC [IsSOIC] p3: isadvanced=TRUE bgadir=Out bgaviamode=Centered fanoutstyle=Auto fanoutdirection=Alternating viagrid=1 // Fanout_SOIC (Default Rule)
FanoutControl Fanout_Default [All] p4: isadvanced=TRUE bgadir=Out bgaviamode=Centered fanoutstyle=Auto fanoutdirection=Alternating viagrid=1 // Fanout_Default (Default Rule)
FanoutControl Fanout_Small [(CompPinCount < 5)] p5: isadvanced=TRUE bgadir=Out bgaviamode=Centered fanoutstyle=Auto fanoutdirection=OutThenIn viagrid=1 // Fanout_Small (Default Rule)
Height [All] p1: isadvanced=TRUE minheight=0 maxheight=1000 prefheight=500
HoleSize [All] p1: isadvanced=TRUE absolutevalues=TRUE maxlimit=251 minlimit=7.87 maxpercent=80.000 minpercent=20.000
HoleToHoleClearance [All] p1: isadvanced=TRUE gap=10 allowstackedmicrovias=TRUE
LayerPairs [All] p1: isadvanced=TRUE enforce=TRUE
MatchedLengths MatchLengths_U9_SOM-ETH1_Passives_U2 [InxSignalClass('xSignals_U9_SOM-ETH1_Passives_U2_MatchLengthsClass')] p1: tolerance=100 checknetsindiffpair=FALSE checkdiffpairvsdiffpair=TRUE checkxsignals=TRUE checkothers=TRUE
MatchedLengths MatchLengths_xSignals_U9_SOM-ETH1_Passives [InxSignalClass('xSignals_U9_SOM-ETH1_Passives_MatchLengthsClass')] p2: tolerance=100 checknetsindiffpair=FALSE checkdiffpairvsdiffpair=TRUE checkxsignals=TRUE checkothers=TRUE
MatchedLengths MatchLengths_xSignals_U9_SOM-ETH1_U2 [InxSignalClass('xSignals_U9_SOM-ETH1_U2_MatchLengthsClass')] p3: tolerance=100 checknetsindiffpair=FALSE checkdiffpairvsdiffpair=TRUE checkxsignals=TRUE checkothers=TRUE
MatchedLengths MatchLengths_xSignals_U2_U9_SOM-ETH2 [InxSignalClass('xSignals_U2_U9_SOM-ETH2_MatchLengthsClass')] p4: tolerance=100 checknetsindiffpair=FALSE checkdiffpairvsdiffpair=TRUE checkxsignals=TRUE checkothers=TRUE
MatchedLengths MatchLengths_xSignals_U2_U9_SOM-ETH1_2 [InxSignalClass('xSignals_U2_U9_SOM-ETH1_MatchLengthsClass')] p5: tolerance=100 checknetsindiffpair=FALSE checkdiffpairvsdiffpair=TRUE checkxsignals=TRUE checkothers=TRUE
MatchedLengths MatchLengths_xSignals_U2_U9_SOM-ETH1_1 [InxSignalClass('xSignals_U2_U9_SOM-ETH1_MatchLengthsClass')] p6: tolerance=100 checknetsindiffpair=FALSE checkdiffpairvsdiffpair=TRUE checkxsignals=TRUE checkothers=TRUE
MatchedLengths MatchLengths_xSignals_U2_U9_SOM-ETH1 [InxSignalClass('xSignals_U2_U9_SOM-ETH1_MatchLengthsClass')] p7: tolerance=100 checknetsindiffpair=FALSE checkdiffpairvsdiffpair=TRUE checkxsignals=TRUE checkothers=TRUE
MinimumAnnularRing MinimumAnnularRing_ThermalPadVias [IsVia and InAnyComponent] p1: isadvanced=TRUE minimumring=4.92
MinimumAnnularRing [All] p2: isadvanced=TRUE minimumring=4.92
MinimumSolderMaskSliver MinimumSolderMaskSliver_Logo [InComponentClass('Logo') vs InComponentClass('Logo')] p1: isadvanced=TRUE minsoldermaskwidth=0.7
MinimumSolderMaskSliver [All] p2: isadvanced=TRUE minsoldermaskwidth=3.94
NetAntennae [All] p1: isadvanced=TRUE netantennaetolerance=0
PasteMaskExpansion [All] p1: isadvanced=TRUE expansion=0
PlaneClearance [All] p1: isadvanced=TRUE clearance=20
PlaneConnect [All] p1: isadvanced=TRUE planeconnectstyle=Relief reliefexpansion=10 reliefentries=4 reliefconductorwidth=10 reliefairgap=10
PolygonConnect PolygonConnect_SMD [HasFootprint('0201*') or HasFootprint('0402*') or HasFootprint('0508') or HasFootprint('0603*') or HasFootprint('0612') or HasFootprint('0805*') or HasFootprint('0815*') or HasFootprint('0830*') or HasFootprint('1206*') or HasFootprint('1210*') or HasFootprint('1808*') or HasFootprint('1812*') or HasFootprint('1825*') or HasFootprint('2010*') or HasFootprint('2220*') or HasFootprint('2225*') or HasFootprint('2512*') or HasFootprint('2728*') or HasFootprint('3518*') or IsVia or HasFootprint('SMC*') or HasFootprint('DQK*') or HasFootprint('SMA') or HasFootprint('DMQ*') or HasFootprint('XFL4015') or HasFootprint('DRV*') or HasFootprint('SloBlo452') or HasFootprint('RDH*') or HasFootprint('*1210*') or HasFootprint('WE-*') or HasFootprint('DRL*') or HasFootprint('PWP*') or HasFootprint('DGN*') or HasFootprint('SMB*') or HasFootprint('DCK*')  or HasFootprint('Abracon*') or HasFootprint('Samtec*') or InComponent('U5') or HasFootprint('DBV*') or HasFootprint('FP-885*') or HasFootprint('FP-744*') or HasFootprint('D0008*') or HasFootprint('DRB*') or HasFootprint('Panasonic*') or InComponent('J6') or InComponent('J7')] p1: connectstyle=Direct reliefconductorwidth=10 reliefentries=4 polygonreliefangle="90 Angle" airgapwidth=10
PolygonConnect [All] p2: connectstyle=Relief reliefconductorwidth=10 reliefentries=4 polygonreliefangle="90 Angle" airgapwidth=10
RoomDefinition RoomDefinition_3 [InComponentClass('Room Definition8') vs False] p1: confinementstyle=ConfineIn formatcopy=TRUE lockcomponents=FALSE outline 1451.35,425.65 1724.35,425.65 1724.35,628.65 1451.35,628.65
RoomDefinition RoomDefinition_7 [InComponentClass('Room Definition10') vs False] p2: confinementstyle=ConfineIn formatcopy=TRUE lockcomponents=FALSE outline 2898,1095 3154,1095 3154,1217 2898,1217
RoomDefinition [InComponentClass('Room Definition7') vs False] p3: confinementstyle=ConfineIn formatcopy=TRUE lockcomponents=FALSE outline 2746,735 3210,735 3210,1133 2746,1133
RoomDefinition RoomDefinition_5 [InComponentClass('Room Definition6') vs False] p4: confinementstyle=ConfineIn formatcopy=TRUE lockcomponents=FALSE outline 2733,1223.32 3237,1223.32 3237,1620.32 2733,1620.32
RoomDefinition RoomDefinition_6 [InComponentClass('Room Definition5') vs False] p5: confinementstyle=ConfineIn formatcopy=TRUE lockcomponents=FALSE outline 1618.35,1042.6 1618.35,1334.6 1462.35,1334.6 1462.35,1042.6
RoomDefinition RoomDefinition_4 [InComponentClass('Room Definition4') vs False] p6: confinementstyle=ConfineIn formatcopy=TRUE lockcomponents=FALSE outline 1876.69,1811.36 2044.69,1811.36 2044.69,2112.36 1876.69,2112.36
RoomDefinition RoomDefinition_1 [InComponentClass('Room Definition2') vs False] p7: confinementstyle=ConfineIn formatcopy=TRUE lockcomponents=FALSE outline 2545.37,1634.91 2187.37,1634.91 2187.37,1317.91 2545.37,1317.91
RoomDefinition SOC_POLY [False] p8: confinementstyle=ConfineIn formatcopy=TRUE lockcomponents=FALSE outline 2127.47,776.34 2127.47,1366.89 2729.83,1366.89 2729.83,776.34
RoomDefinition RoomDefinition_2 [InComponentClass('RAM') vs False] p9: confinementstyle=ConfineIn formatcopy=TRUE lockcomponents=FALSE outline 1845,1751 1845,2185 1485,2185 1485,1751
RoomDefinition SOM-ETH2 [InComponentClass('SOM-ETH2')] p10: isadvanced=TRUE confinementstyle=ConfineIn formatcopy=TRUE lockcomponents=FALSE outline 1454.13,747.64 1986.7,747.64 1986.7,1169.64 1454.13,1169.64
RoomDefinition SOM-ETH1 [InComponentClass('SOM-ETH1') vs False] p11: isadvanced=TRUE confinementstyle=ConfineIn formatcopy=TRUE lockcomponents=FALSE outline 1455.13,1190.64 1987.7,1190.64 1987.7,1612.64 1455.13,1612.64
RoutingCorners [All] p1: isadvanced=TRUE cornerstyle=45-Degree minsetback=100 maxsetback=100
RoutingPriority [All] p1: isadvanced=TRUE routingpriority=0
RoutingVias [All] p1: holewidth=8 width=18 viastyle="Through Hole" minholewidth=7 minwidth=16 maxholewidth=28 maxwidth=50
ShortCircuit [All] p1: isadvanced=TRUE allowed=FALSE
SilkToBoardRegionClearance [Not ((IsComment or IsDesignator) And (Hide <> 'False')) and not InRegion(1000,500,4000,800)] p1:
SilkToSilkClearance SilkToSilkClearance_Pb-FreeLogo [(HasFootprint('Pb-Free_Overlay_Medium') OR HasFootprint('Pb-Free_Overlay_Small')) vs (HasFootprint('Pb-Free_Overlay_Medium') OR HasFootprint('Pb-Free_Overlay_Small'))] p1: isadvanced=TRUE silktosilkclearance=0
SilkToSilkClearance [All] p2: isadvanced=TRUE silktosilkclearance=3.94
SilkToSolderMaskClearance SilkToComponentPadClearance [(IsPad or IsFill or IsRegion) and InAnycomponent] p1: isadvanced=TRUE minsilkscreentomaskgap=3.94 clearancetoexposedcopper=TRUE
SilkToSolderMaskClearance "Silk to Solder Mask Opening" [All] p2: isadvanced=TRUE minsilkscreentomaskgap=3.94 clearancetoexposedcopper=FALSE
SlopeFalling [InNetClass('MMC')] p1: isadvanced=TRUE maxslope=1.000n
SlopeRising [InNetClass('MMC')] p1: isadvanced=TRUE maxslope=1.000n
SolderMaskExpansion [All] p1: isadvanced=TRUE expansion=1.97 istentingtop=FALSE
SupplyNets "Schematic Supply Nets_43" [InNet('EARTH_GND')] p1: voltage=0.000
SupplyNets "Schematic Supply Nets_42" [InNet('VSYS_USB_5V')] p2: voltage=0.000
SupplyNets "Schematic Supply Nets_41" [InNet('VSYS_1V8')] p3: voltage=0.000
SupplyNets "Schematic Supply Nets_40" [InNet('VBUS_XDS_5V')] p4: voltage=0.000
SupplyNets "Schematic Supply Nets_39" [InNet('VDD_XDS3V3')] p5: voltage=0.000
SupplyNets "Schematic Supply Nets_38" [InNet('5V')] p6: voltage=0.000
SupplyNets "Schematic Supply Nets_37" [InNet('VCORE_1V25')] p7: voltage=0.000
SupplyNets "Schematic Supply Nets_36" [InNet('VUSB_5V')] p8: voltage=0.000
SupplyNets "Schematic Supply Nets_34" [InNet('SHIELD_USB')] p9: voltage=0.000
SupplyNets "Schematic Supply Nets_33" [InNet('V_IN')] p10: voltage=0.000
SupplyNets "Schematic Supply Nets_32" [InNet('VBUS_XDS')] p11: voltage=0.000
SupplyNets "Schematic Supply Nets_31" [InNet('SHIELD_XDS')] p12: voltage=0.000
SupplyNets "Schematic Supply Nets_30" [InNet('SHIELD_USB2')] p13: voltage=0.000
SupplyNets "Schematic Supply Nets_29" [InNet('VDDA_AM261_3V3')] p14: voltage=0.000
SupplyNets "Schematic Supply Nets_28" [InNet('GND_XDS')] p15: voltage=0.000
SupplyNets "Schematic Supply Nets_27" [InNet('V_PLUG')] p16: voltage=0.000
SupplyNets "Schematic Supply Nets_26" [InNet('VSYS_3V3')] p17: voltage=0.000
SupplyNets "Schematic Supply Nets_25" [InNet('VBUS_MICRO_AB_5V0')] p18: voltage=0.000
SupplyNets "Schematic Supply Nets_24" [InNet('VDDA18_AM261_OSC_PL')] p19: voltage=0.000
SupplyNets "Schematic Supply Nets_23" [InNet('VDDA_AM261_1V8_LDO')] p20: voltage=0.000
SupplyNets "Schematic Supply Nets_22" [InNet('GND')] p21: voltage=0.000
UnRoutedNet [All] p1: isadvanced=TRUE checkbadconnections=TRUE
UnpouredPolygon [All] p1: isadvanced=TRUE
Width Width_SE50 [InNetClass('MII0_TX') or InNetClass('MII1_TX') or InNetClass('MII0_RX') or InNetClass('MII1_RX')] p1: maxlimit=10 minlimit=3.5 preferedwidth=10 toplayer_maxwidth=9 toplayer_prefwidth=4.3 midlayer2_maxwidth=4.5 midlayer2_prefwidth=4.5 midlayer5_maxwidth=4.5 midlayer5_prefwidth=4.5 bottomlayer_maxwidth=4.3 bottomlayer_prefwidth=4.3 minimp=50.000000 maximp=50.000000 favimp=50.000000
Width [All] p2: maxlimit=118.11 minlimit=3.5 preferedwidth=6 midlayer1_minwidth=4.5 midlayer2_minwidth=4.5 midlayer3_minwidth=4.5 midlayer4_minwidth=4.5 midlayer5_minwidth=4.5 midlayer6_minwidth=4.5 bottomlayer_minwidth=4.3 minimp=50.000000 maximp=50.000000 favimp=50.000000 checkconnectedcopper=TRUE
2 further rules are at their usual default settings.

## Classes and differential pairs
component class "Room Definition11": C111 J5 R93 U21
component class "Room Definition10": C62 C175 R7 R8 R193 U6 U29
component class "Room Definition9": C175 R8 R193 U29
component class "Room Definition8": C121 C176 R15 R99 R100 TP6 TP29 U7
component class "Room Definition7": C82 C83 C84 C85 R16 R33 R34 R35 R36 R37 R38 R39 R40 R41 R42 R43 R44 R45 R46 R47 R48 R49 R50 R51 R52 R53 R54 R120 R182 R184 R212 U10
component class "Room Definition6": C20 C21 C22 C23 C24 C25 C26 C43 C44 C188 C189 L1 L2 L3 R194 R195 R196 R197 R202 TP32 TP33 U1
component class "Room Definition5": C63 C207 C208 U5 U53
component class "Room Definition4": C86 R55 R56 R57 R169 U11
component class "Room Definition3": C121 C176 R15 R99 R100 U7
component class "Room Definition2": C64 C65 C66 C67 C68 L17 L18 R18 R19 R20 R21 R22 R198 R199 R200 TP1 U8
component class "Room Definition1": C64 C65 C66 C67 C68 L17 L18 R18 R19 R20 R22 R198 R199 R200 TP1 U8
net class OSPI_PSRAM: OSPI1_CLK OSPI1_CSN0 OSPI1_D0 OSPI1_D1 OSPI1_D2 OSPI1_D3 OSPI1_D4 OSPI1_D5 OSPI1_D6 OSPI1_D7 OSPI1_DQS
net class OSPI_FLASH: OSPI0_CLK OSPI0_CSN0 OSPI0_D0 OSPI0_D1 OSPI0_D2 OSPI0_D3 OSPI0_D4 OSPI0_D5 OSPI0_D6 OSPI0_D7 OSPI0_DQS
net class MII1_TX: MTn_CLK_SOM-ETH2 PR0_MII1_TXD0 PR0_MII1_TXD1 PR0_MII1_TXD2 PR0_MII1_TXD3 PR0_MII1_TXEN
net class MII1_RX: MRn_CLK_SOM-ETH2 PR0_MII1_RXD0 PR0_MII1_RXD1 PR0_MII1_RXD2 PR0_MII1_RXD3 PR0_MII1_RXDV PR0_MII1_RXER
net class MII0_TX: MTn_CLK_SOM-ETH1 PR0_MII0_TXD0 PR0_MII0_TXD1 PR0_MII0_TXD2 PR0_MII0_TXD3 PR0_MII0_TXEN
net class MII0_RX: MRn_CLK_SOM-ETH1 PR0_MII0_RXD0 PR0_MII0_RXD1 PR0_MII0_RXD2 PR0_MII0_RXD3 PR0_MII0_RXDV PR0_MII0_RXER
component class "Mounting Holes": H1 H2
channel class TIDA-010973_SOM_Ethernet: SOM-ETH1 SOM-ETH2
net class PR1_PRU1_GPIO[19..0]: PR1_PRU1_GPIO0 PR1_PRU1_GPIO1 PR1_PRU1_GPIO2 PR1_PRU1_GPIO3 PR1_PRU1_GPIO4 PR1_PRU1_GPIO5 PR1_PRU1_GPIO6 PR1_PRU1_GPIO7 PR1_PRU1_GPIO8 PR1_PRU1_GPIO9 PR1_PRU1_GPIO10 PR1_PRU1_GPIO11 PR1_PRU1_GPIO12 PR1_PRU1_GPIO13 PR1_PRU1_GPIO14 PR1_PRU1_GPIO15 PR1_PRU1_GPIO16 PR1_PRU1_GPIO17 PR1_PRU1_GPIO18 PR1_PRU1_GPIO19
net class PR1_PRU0_GPIO[20..0]: PR1_PRU0_GPIO0 PR1_PRU0_GPIO1 PR1_PRU0_GPIO2 PR1_PRU0_GPIO3 PR1_PRU0_GPIO4 PR1_PRU0_GPIO5 PR1_PRU0_GPIO6 PR1_PRU0_GPIO7 PR1_PRU0_GPIO8 PR1_PRU0_GPIO9 PR1_PRU0_GPIO10 PR1_PRU0_GPIO11 PR1_PRU0_GPIO12 PR1_PRU0_GPIO13 PR1_PRU0_GPIO14 PR1_PRU0_GPIO15 PR1_PRU0_GPIO16 PR1_PRU0_GPIO17 PR1_PRU0_GPIO18 PR1_PRU0_GPIO19 PR1_PRU0_GPIO20
net class PR0_MII1_TXD[3..0]: PR0_MII1_TXD0 PR0_MII1_TXD1 PR0_MII1_TXD2 PR0_MII1_TXD3
net class PR0_MII1_RXD[3..0]: PR0_MII1_RXD0 PR0_MII1_RXD1 PR0_MII1_RXD2 PR0_MII1_RXD3
net class PR0_MII0_TXD[3..0]: PR0_MII0_TXD0 PR0_MII0_TXD1 PR0_MII0_TXD2 PR0_MII0_TXD3
net class PR0_MII0_RXD[3..0]: PR0_MII0_RXD0 PR0_MII0_RXD1 PR0_MII0_RXD2 PR0_MII0_RXD3
net class PR0_IEP0_EDC_SYNC_OUT[1..0]: PR0_IEP0_EDC_SYNC_OUT0 PR0_IEP0_EDC_SYNC_OUT1
net class PR0_IEP0_EDC_LATCH_IN[1..0]: PR0_IEP0_EDC_LATCH_IN0 PR0_IEP0_EDC_LATCH_IN1
net class OSPI1_D[7..0]: OSPI1_D0 OSPI1_D1 OSPI1_D2 OSPI1_D3 OSPI1_D4 OSPI1_D5 OSPI1_D6 OSPI1_D7
net class OSPI0_D[7..0]: OSPI0_D0 OSPI0_D1 OSPI0_D2 OSPI0_D3 OSPI0_D4 OSPI0_D5 OSPI0_D6 OSPI0_D7
net class MMC0_D[3..0]: MMC0_D0 MMC0_D1 MMC0_D2 MMC0_D3
net class HPI_IRQ[3..0]: HPI_IRQ0 HPI_IRQ1 HPI_IRQ2 HPI_IRQ3
net class AM261_SOP[3..0]: AM261_SOP0 AM261_SOP1 AM261_SOP2 AM261_SOP3
component class USB: C125 C126 C127 C128 C129 C130 C131 C132 C133 C134 C135 C136 C137 C138 D18 D19 J13 J14 J20 L9 L10 L11 R132 R133 R134 R135 R136 R137 R138 R139 R140 R141 R142 R143 R144 TP8 TP9 U33 U34 U35 U36 U37 U38 U39
component class UI: C111 C112 C113 C114 C115 C116 C177 D7 D8 D10 D11 D12 D13 D14 D15 D16 D17 D23 J5 Q9 Q10 Q11 Q12 Q13 R12 R89 R90 R91 R92 R93 R94 R95 R96 R98 R103 R105 R107 R108 R109 R110 R111 R114 R115 R116 R117 R213 SH-J1 SW1 SW2 SW3 TP7 TP30 U21 U22 U23 U24 U25
component class SOM-Power: C1 C2 C3 C4 C5 C6 C7 C8 C9 C10 C11 C12 C13 C14 C15 C16 C17 C18 C19 C20 C21 C22 C23 C24 C25 C26 C27 C28 C29 C30 C31 C32 C33 C34 C35 C36 C37 C38 C39 C40 C41 C42 C43 C44 C45 C48 C49 C50 C51 C52 C53 C54 C55 C56 C57 C58 C59 C60 C188 C189 C190 C198 C199 C200 C201 C202 C203 C204 C205 C206 C209 C210 D1 D2 D3 L1 L2 L3 L13 L14 L15 Q1 Q2 R1 R2 R3 R4 R5 R11 R194 R195 R196 R197 R202 TP32 TP33 U1
component class SOM-MEM: C82 C83 C84 C85 C86 R33 R34 R35 R36 R37 R38 R39 R40 R41 R42 R43 R44 R45 R46 R47 R48 R49 R50 R51 R52 R53 R54 R55 R56 R57 R169 U10 U11
component class SOM-MCU: C61 C62 C63 C64 C65 C66 C67 C68 C120 C121 C123 C175 C176 C178 C207 C208 C212 C213 C214 C215 C216 C217 L17 L18 R6 R7 R8 R9 R10 R13 R14 R15 R16 R17 R18 R19 R20 R21 R22 R99 R100 R120 R121 R123 R181 R182 R183 R184 R185 R193 R198 R199 R200 R208 R209 R210 R211 R212 R217 R218 R219 R227 R228 R229 R230 R231 R232 R234 R235 R236 R237 R238 TP1 TP6 TP29 U2 U3 U4 U5 U6 U7 U8 U29 U31 U47 U53
component class SOM-ETH2: C69_SOM-ETH2 C70_SOM-ETH2 C71_SOM-ETH2 C72_SOM-ETH2 C73_SOM-ETH2 C74_SOM-ETH2 C75_SOM-ETH2 C76_SOM-ETH2 C77_SOM-ETH2 C78_SOM-ETH2 C79_SOM-ETH2 C80_SOM-ETH2 C81_SOM-ETH2 C191_SOM-ETH2 L4_SOM-ETH2 L5_SOM-ETH2 R23_SOM-ETH2 R24_SOM-ETH2 R25_SOM-ETH2 R26_SOM-ETH2 R27_SOM-ETH2 R28_SOM-ETH2 R29_SOM-ETH2 R30_SOM-ETH2 R31_SOM-ETH2 R32_SOM-ETH2 R201_SOM-ETH2 R204_SOM-ETH2 R205_SOM-ETH2 R206_SOM-ETH2 R207_SOM-ETH2 R233_SOM-ETH2 U9_SOM-ETH2
component class SOM-ETH1: C69_SOM-ETH1 C70_SOM-ETH1 C71_SOM-ETH1 C72_SOM-ETH1 C73_SOM-ETH1 C74_SOM-ETH1 C75_SOM-ETH1 C76_SOM-ETH1 C77_SOM-ETH1 C78_SOM-ETH1 C79_SOM-ETH1 C80_SOM-ETH1 C81_SOM-ETH1 C191_SOM-ETH1 L4_SOM-ETH1 L5_SOM-ETH1 R23_SOM-ETH1 R24_SOM-ETH1 R25_SOM-ETH1 R26_SOM-ETH1 R27_SOM-ETH1 R28_SOM-ETH1 R29_SOM-ETH1 R30_SOM-ETH1 R31_SOM-ETH1 R32_SOM-ETH1 R201_SOM-ETH1 R204_SOM-ETH1 R205_SOM-ETH1 R206_SOM-ETH1 R207_SOM-ETH1 R233_SOM-ETH1 U9_SOM-ETH1
component class RAM: C184 C185 C186 C187 R66 R67 R68 R69 R70 R71 R72 R73 R74 R75 R76 R77 R78 R79 R80 R81 R82 R83 R187 R188 R189 R190 R191 U16
component class PWR: C46 C87 C88 C89 C90 C91 C92 C93 C94 C95 C96 C97 C98 C99 C100 C101 D4 D5 D6 F1 J1 L6 L7 L8 Q3 Q4 R58 R59 R60 R61 R62 R63 R64 R65 TP2 TP3 TP4 TP5 U12 U13 U14 U15
component class JTAG: C139 C140 C141 C142 C143 C144 C145 C146 C147 C148 C149 C150 C151 C152 C153 C154 C155 C156 C157 C158 C159 C160 C161 C162 C163 C164 C165 C166 C167 C168 C169 C170 C171 C183 D20 D21 D22 J15 J16 J17 L12 R145 R146 R147 R148 R149 R150 R151 R152 R153 R154 R155 R156 R157 R158 R159 R160 R161 R162 R163 R164 R165 R166 R167 R168 R186 R192 R223 R224 R225 R226 R239 R240 R241 R242 TP10 TP11 TP12 TP13 TP14 TP15 TP16 TP17 TP18 TP19 TP20 TP21 TP22 TP23 TP24 TP25 TP26 TP27 TP31 U40 U41 U42 U43 U44 U45 U46 U51 Y1
component class HPI: C117 C118 C119 C179 C180 C181 C182 C193 C196 C197 C211 C218 C219 J6 J7 J8 J9 J10 J11 J12 J18 L16 R118 R119 R175 R176 R177 R178 R179 R180 R220 R221 R222 SH-J2 U19 U26 U27 U28 U49 U50 U52 U54 U55
component class ETH: C102 C103 C104 C105 C106 C107 C108 C109 C110 J2 J3 J4 Q5 Q6 Q7 Q8 R84 R85 R86 R87 R88 U17 U57
component class CFG: C122 C124 C172 C173 C174 C192 C194 C195 D24 Q14 R112 R113 R122 R124 R125 R126 R127 R128 R129 R130 R131 R171 R172 R173 R214 R215 R216 SW4 SW5 SW6 U20 U30 U32 U48
component class Shunt: SH-J1 SH-J2
component class Header: J5 J7 J8 J9 J12 J16 J17 J18 J20
component class Logo: Logo1
component class Hw: FID1 FID2 FID3 FID4 FID5 FID6 H1 H2 LBL1 Logo1 Logo2 Logo3 Logo4 MH1 MH2 MH3 MH4 ZZ1 ZZ2 ZZ3 ZZ4
component class FiducialMark: FID1 FID2 FID3 FID4 FID5 FID6
component class AssemblyNote: ZZ1 ZZ2 ZZ3 ZZ4
component class Label: LBL1
differential pair AM261_USB0_D: +AM261_USB0_D_P -AM261_USB0_D_N
differential pair XDSET_1_D: +XDSET_1_D_P -XDSET_1_D_N
differential pair ETH1_TD: +ETH1_TD_P -ETH1_TD_N
differential pair ETH1_RD: +ETH1_RD_P -ETH1_RD_N
differential pair ETH0_TD: +ETH0_TD_P -ETH0_TD_N
differential pair ETH0_RD: +ETH0_RD_P -ETH0_RD_N

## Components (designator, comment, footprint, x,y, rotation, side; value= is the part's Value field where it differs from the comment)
C1 "885012104005" FP-885012104005_0201-IPC_C 2498.01,1186 r0 bottom value=100nF
C2 "885012104005" FP-885012104005_0201-IPC_C 2384,970 r270 bottom value=100nF
C3 "885012104005" FP-885012104005_0201-IPC_C 2461,970 r270 bottom value=100nF
C4 "885012104005" FP-885012104005_0201-IPC_C 2499.01,956 r0 bottom value=100nF
C5 "885012104005" FP-885012104005_0201-IPC_C 2538,1018.01 r90 bottom value=100nF
C6 "885012104005" FP-885012104005_0201-IPC_C 2319.99,981 r180 bottom value=100nF
C7 "885012104005" FP-885012104005_0201-IPC_C 2345.99,956 r180 bottom value=100nF
C8 "885012104005" FP-885012104005_0201-IPC_C 2307.36,1177.57 r270 bottom value=100nF
C9 "885012104005" FP-885012104005_0201-IPC_C 2538,1147.01 r90 bottom value=100nF
C10 "885012104005" FP-885012104005_0201-IPC_C 2319.99,1110 r180 bottom value=100nF
C11 "885012104005" FP-885012104005_0201-IPC_C 2524.01,1110 r0 bottom value=100nF
C12 "885012104005" FP-885012104005_0201-IPC_C 2319.99,1033 r180 bottom value=100nF
C13 "885012104005" FP-885012104005_0201-IPC_C 2526.01,982 r0 bottom value=100nF
C14 "C1005X5R1A335K050BC" 0402L 2515.45,876.55 r0 bottom value=3.3uF
C15 "C1005X5R1A335K050BC" 0402L 2329.68,1140 r0 bottom value=3.3uF
C16 "C1005X5R1A335K050BC" 0402L 2614.96,1277.57 r0 bottom value=3.3uF
C17 "885012104005" FP-885012104005_0201-IPC_C 2565.17,1096.45 r90 bottom value=100nF
C18 "885012104005" FP-885012104005_0201-IPC_C 2282,1122 r270 bottom value=100nF
C19 "885012104005" FP-885012104005_0201-IPC_C 2295,931 r180 bottom value=100nF
C20 "885012107011" 0805_150 3165.13,1375.95 r180 top value=22uF
C21 "885012107011" 0805_150 3164.8,1376.1 r180 bottom value=22uF
C22 "C1005X5R1A475K050BC" 0402_065S 3096,1453.78 r270 top value=4.7uF
C23 "C1005X5R1A475K050BC" 0402_065S 2987.13,1288.95 r270 top value=4.7uF
C24 "C1005X5R1A475K050BC" 0402_065S 2877.13,1452.95 r270 top value=4.7uF
C25 "C1005X5R1A475K050BC" 0402_065S 2877,1392.32 r90 top value=4.7uF
C26 "885012107011" 0805_150 2780.13,1353.95 r90 top value=22uF
C27 "885012104005" FP-885012104005_0201-IPC_C 2499,931 r0 bottom value=100nF
C28 "885012104005" FP-885012104005_0201-IPC_C 2495.86,1213.64 r0 bottom value=100nF
C29 "885012104005" FP-885012104005_0201-IPC_C 2346,1212 r180 bottom value=100nF
C30 "885012104005" FP-885012104005_0201-IPC_C 2575.99,982 r180 bottom value=100nF
C31 "885012104005" FP-885012104005_0201-IPC_C 2396.99,931 r180 bottom value=100nF
C32 "885012104005" FP-885012104005_0201-IPC_C 2282,1020.01 r90 bottom value=100nF
C33 "885012104005" FP-885012104005_0201-IPC_C 2563,1018.01 r90 bottom value=100nF
C34 "885012104005" FP-885012104005_0201-IPC_C 2281.61,1178.12 r270 bottom value=100nF
C35 "C1005X5R1A335K050BC" 0402L 2317,1080 r0 bottom value=3.3uF
C36 "C1005X5R1A335K050BC" 0402L 2432,1181 r180 bottom value=3.3uF
C37 "C1005X5R1A335K050BC" 0402L 2534,1292 r0 bottom value=3.3uF
C38 "C1005X5R1A335K050BC" 0402L 2539,1060 r180 bottom value=3.3uF
C39 "C1005X5R1A335K050BC" 0402L 2199.3,1135 r270 bottom value=3.3uF
C40 "885012104005" FP-885012104005_0201-MFG 2589,1024 r270 bottom value=100nF
C41 "885012104005" FP-885012104005_0201-MFG 2346.66,906 r0 bottom value=100nF
C42 "885012104005" FP-885012104005_0201-IPC_C 2410,1249.99 r270 bottom value=100nF
C43 "885012107011" 0805_150 2780.8,1494.54 r270 top value=22uF
C44 "885012106018" 0603L 3077.13,1284.39 r270 top value=2.2uF
C45 "885012104005" FP-885012104005_0201-IPC_C 2436.15,1251.29 r270 bottom value=100nF
C46 "885012208094" FP-885012208094_1206-MFG 428,3279 r0 bottom
C48 "885012104005" FP-885012104005_0201-IPC_C 2468.94,1240.32 r0 bottom value=100nF
C49 "C1005X5R1A335K050BC" 0402L 2640.37,984.56 r270 bottom value=3.3uF
C50 "C1005X5R1A335K050BC" 0402L 2207,918 r270 bottom value=3.3uF
C51 "C1005X5R1A335K050BC" 0402L 2360.15,1248.48 r180 bottom value=3.3uF
C52 "885012104005" FP-885012104005_0201-IPC_C 2494.15,1377.47 r270 bottom value=100nF
C53 "885012104005" FP-885012104005_0201-IPC_C 2271.99,1058 r180 bottom value=100nF
C54 "885012104005" FP-885012104005_0201-IPC_C 2606,1434 r180 bottom value=100nF
C55 "885012104005" FP-885012104005_0201-IPC_C 2400.99,1212 r180 bottom value=100nF
C56 "C1005X5R1A335K050BC" 0402L 2606.68,1403 r0 bottom value=3.3uF
C57 "C1005X5R1A335K050BC" 0402L 2678,1403 r180 bottom value=3.3uF
C58 "C1005X5R1A335K050BC" 0402L 2646.71,1335.66 r0 bottom value=3.3uF
C59 "885012104005" FP-885012104005_0201-IPC_C 2679.79,1435.36 r0 bottom value=100nF
C60 "885012104005" FP-885012104005_0201-IPC_C 2600,1160 r0 bottom value=100nF
C61 "885012105010" 0402L 1865.98,691.52 r180 top value=0.1uF
C62 "885012105010" 0402L 3005.68,1174 r0 top value=0.1uF
C63 "885012205037" 0402L 1581,1077 r0 bottom value=0.1uF
C64 "885012205037" 0402L 2472.21,1547.53 r0 top value=0.1uF
C65 "885012205037" 0402L 2237.72,1561.91 r180 top value=0.1uF
C66 "885012205037" 0402L 2335.23,1397.18 r270 top value=0.1uF
C67 "885012205037" 0402L 2472.21,1516.03 r0 top value=0.1uF
C68 "885012205037" 0402L 2471.94,1484.2 r180 top value=0.1uF
C69_SOM-ETH1 "885012205031" 0402L 1930.13,1323.47 r0 top value=0.01uF (schematic designator C69)
C69_SOM-ETH2 "885012205031" 0402L 1929.13,880.47 r0 top value=0.01uF (schematic designator C69)
C70_SOM-ETH1 "885012205037" 0402L 1930.13,1290.99 r0 top value=0.1uF (schematic designator C70)
C70_SOM-ETH2 "885012205037" 0402L 1929.13,847.99 r0 top value=0.1uF (schematic designator C70)
C71_SOM-ETH1 "885012105012" 0402L 1930.13,1290.99 r0 bottom value=1uF (schematic designator C71)
C71_SOM-ETH2 "885012105012" 0402L 1929.13,847.99 r0 bottom value=1uF (schematic designator C71)
C72_SOM-ETH1 "GRM155R61A106ME11D" 0402L 1930.13,1323.47 r0 bottom value=10uF (schematic designator C72)
C72_SOM-ETH2 "GRM155R61A106ME11D" 0402L 1929.13,880.47 r0 bottom value=10uF (schematic designator C72)
C73_SOM-ETH1 "885012205031" 0402L 1582.13,1453.16 r180 top value=0.01uF (schematic designator C73)
C73_SOM-ETH2 "885012205031" 0402L 1581.13,1010.16 r180 top value=0.01uF (schematic designator C73)
C74_SOM-ETH1 "885012205037" 0402L 1582.13,1420.68 r180 top value=0.1uF (schematic designator C74)
C74_SOM-ETH2 "885012205037" 0402L 1581.13,977.68 r180 top value=0.1uF (schematic designator C74)
C75_SOM-ETH1 "885012105012" 0402L 1582.13,1420.68 r180 bottom value=1uF (schematic designator C75)
C75_SOM-ETH2 "885012105012" 0402L 1581.13,977.68 r180 bottom value=1uF (schematic designator C75)
C76_SOM-ETH1 "GRM155R61A106ME11D" 0402L 1582.13,1453.16 r180 bottom value=10uF (schematic designator C76)
C76_SOM-ETH2 "GRM155R61A106ME11D" 0402L 1581.13,1010.16 r180 bottom value=10uF (schematic designator C76)
C77_SOM-ETH1 "GRM1555C1H4R7CA01D" 0402L 1201,1879.68 r90 bottom value=4.7pF (schematic designator C77)
C77_SOM-ETH2 "GRM1555C1H4R7CA01D" 0402L 1202,648.68 r90 bottom value=4.7pF (schematic designator C77)
C78_SOM-ETH1 "GRM1555C1H4R7CA01D" 0402L 1234,1907.68 r90 bottom value=4.7pF (schematic designator C78)
C78_SOM-ETH2 "GRM1555C1H4R7CA01D" 0402L 1234,673.68 r90 bottom value=4.7pF (schematic designator C78)
C79_SOM-ETH1 "GRM1555C1H4R7CA01D" 0402L 1201,1797.32 r270 bottom value=4.7pF (schematic designator C79)
C79_SOM-ETH2 "GRM1555C1H4R7CA01D" 0402L 1202,567.32 r270 bottom value=4.7pF (schematic designator C79)
C80_SOM-ETH1 "GRM1555C1H4R7CA01D" 0402L 1234,1824.32 r270 bottom value=4.7pF (schematic designator C80)
C80_SOM-ETH2 "GRM1555C1H4R7CA01D" 0402L 1234,592.32 r270 bottom value=4.7pF (schematic designator C80)
C81_SOM-ETH1 "885012205008" 0402L 1582.13,1485.64 r0 top value=2200pF (schematic designator C81)
C81_SOM-ETH2 "885012205008" 0402L 1581.13,1042.64 r0 top value=2200pF (schematic designator C81)
C82 "885012205037" 0402L 2936,987 r270 bottom value=0.1uF
C83 "885012205037" 0402L 3054,1026 r90 bottom value=0.1uF
C84 "885012205037" 0402L 2996,888 r180 bottom value=0.1uF
C85 "GRM155R61A106ME18D" FP-GRM155R61A106ME18D_0402-MFG 3005.8,783.64 r90 top value=10µF
C86 "885012205037" 0402L 2016,1907 r270 top value=0.1uF
C87 "EMK105BJ105KVHF" 0402L 1722.41,3525.65 r0 top value=1uF
C88 "885012209074" FP-885012209074_1210-IPC_C 1766.66,3150.65 r180 top value=22µF
C89 "885012209074" FP-885012209074_1210-IPC_C 1553.41,3150.65 r0 top value=22µF
C90 "885012209074" FP-885012209074_1210-IPC_C 1766.66,3150.65 r180 bottom value=22µF
C91 "EEE-FP1V470AP" Panasonic_SMT_630x580 1232,3308 r270 top value=47uF
C92 "885012205086" FP-885012205086_0402-IPC_C 1802.41,3450.65 r180 top value=100nF
C93 "885012205086" FP-885012205086_0402-IPC_C 1523.41,3451.65 r0 top value=100nF
C94 "885012209048" FP-885012209048_1210-IPC_C 1500.41,3354.65 r90 top value=4.7µF
C95 "885012209048" FP-885012209048_1210-IPC_C 1825.41,3354.65 r90 top value=4.7µF
C96 "GRM32ER71H106KA12L" 1210_270L 986,3213 r0 top value=10uF
C97 "885012205086" FP-885012205086_0402-IPC_A 843,3548 r270 top value=100nF
C98 "885012205086" FP-885012205086_0402-MFG 800.32,3125.31 r180 top value=100nF
C99 "885012005009" 0402L 1643,3560 r180 top value=22pF
C100 "885012205086" FP-885012205086_0402-IPC_C 1169.68,3009 r270 top value=100nF
C101 "885012205086" FP-885012205086_0402-IPC_C 1169.68,3076 r90 top value=100nF
C102 "885012206052" 0603L 1021.35,1955 r0 bottom value=1uF
C103 "885012206052" 0603L 1021.35,717 r0 bottom value=1uF
C104 "885012206046" 0603L 1021.35,1909 r0 bottom value=0.1uF
C105 "885012206046" 0603L 1021.35,671 r0 bottom value=0.1uF
C106 "885012206052" 0603L 1021.35,1808 r0 bottom value=1uF
C107 "885012206052" 0603L 1021.35,568 r0 bottom value=1uF
C108 "885012206046" 0603L 1021.35,1761 r0 bottom value=0.1uF
C109 "885012206046" 0603L 1021.35,522 r0 bottom value=0.1uF
C110 "1812GC102KA1" 1812_254 658.32,1236.68 r0 bottom value=1000pF
C111 "885012105010" 0402L 2481,516 r90 bottom value=0.1uF
C112 "885012105010" 0402L 605,2576 r180 bottom value=0.1uF
C113 "885012105010" 0402L 876,2386 r270 bottom value=0.1uF
C114 "04026D474KAT2A" 0402L 128.81,2489.22 r270 bottom value=0.47uF
C115 "885012105010" 0402L 907,2930 r0 bottom value=0.1uF
C116 "885012105010" 0402L 155,2578 r90 bottom value=0.1uF
C117 "885012205037" 0402L 4312,675 r0 top value=0.1uF
C118 "885012205037" 0402L 4485,682 r0 top value=0.1uF
C119 "885012205037" 0402L 4064,539 r0 top value=0.1uF
C120 "885012105010" 0402L 2645,1564 r180 bottom value=0.1uF
C121 "885012105010" 0402L 1557,452 r90 top value=0.1uF
C122 "885012105010" 0402L 1642.24,284.46 r180 top value=0.1uF
C123 "885012105010" 0402L 1575,350 r90 bottom value=0.1uF
C124 "885012105010" 0402L 1642.24,220.65 r180 top value=0.1uF
C125 "885012106031" FP-885012106031_0603-IPC_C 2086.32,3252 r90 top value=10µF
C126 "885012106031" FP-885012106031_0603-IPC_C 1968.32,3252 r270 top value=10µF
C127 "GRM155R62A104KE14D" 0402L 2127.32,3252 r270 top value=0.1uF
C128 "GRM155R62A104KE14D" 0402L 2402,3047 r0 top value=0.1uF
C129 "1812GC102KA1" 1812_254 3246.32,3508 r270 bottom value=1000pF
C130 "885012106031" FP-885012106031_0603-IPC_C 1970,3137.28 r0 top value=10µF
C131 "885012106031" FP-885012106031_0603-IPC_C 2116,3136.28 r180 top value=10µF
C132 "GRM155R62A104KE14D" 0402L 1946.33,3086.28 r180 top value=0.1uF
C133 "GRM155R62A104KE14D" 0402L 2132,3087 r0 top value=0.1uF
C134 "GCM155R71H102KA37D" 0402L 2132,3055 r180 top value=1000pF
C135 "885012106031" FP-885012106031_0603-IPC_C 3256,3299 r180 top value=10µF
C136 "GRM155R62A104KE14D" 0402 3255,3340 r0 top value=0.1uF
C137 "GRM155R62A104KE14D" 0402L 2377,2894.81 r0 top value=0.1uF
C138 "1812GC102KA1" 1812_254 2303,3469 r90 bottom value=1000pF
C139 "885012205037" 0402L 3282.67,3128.35 r180 bottom value=0.1uF
C140 "04023C103JAT2A" 0402L 4002,3199.69 r90 bottom value=0.01uF
C141 "1812GC102KA1" 1812_254 4250,3499.74 r270 bottom value=1000pF
C142 "885012106031" FP-885012106031_0603-IPC_C 4686,3303 r180 top value=10µF
C143 "GRM155R62A104KE14D" 0402L 4715,3385 r270 top value=0.1uF
C144 "885012106031" FP-885012106031_0603-IPC_C 4756,3388 r90 top value=10µF
C145 "885012205037" 0402L 3624,2006 r270 bottom value=0.1uF
C146 "885012205037" 0402L 3579,2008 r270 bottom value=0.1uF
C147 "885012205037" 0402L 4100,2005 r270 bottom value=0.1uF
C148 "885012205037" 0402L 3624,2240 r90 bottom value=0.1uF
C149 "885012205037" 0402L 3579,2242 r90 bottom value=0.1uF
C150 "885012205037" 0402L 4100,2239 r90 bottom value=0.1uF
C151 "1812GC102KA1" 1812_254 3261,2131 r270 bottom value=1000pF
C152 "885012205037" 0402L 3268.31,2618 r0 bottom value=0.1uF
C153 "885012105012" 0402L 3530,3227 r90 bottom value=1uF
C154 "885012205037" 0402L 4102,2979 r0 bottom value=0.1uF
C155 "885012205037" 0402L 4102,2846 r0 bottom value=0.1uF
C156 "04023C103JAT2A" 0402L 3342,3022 r90 bottom value=0.01uF
C157 "04023C103JAT2A" 0402L 4102,2676 r0 bottom value=0.01uF
C158 "04023C103JAT2A" 0402L 3844,2435 r270 bottom value=0.01uF
C159 "GCM1555C1H8R0DA16D" 0402L 3307.01,2920.3 r270 bottom
C160 "GCM1555C1H8R0DA16D" 0402L 3306.01,3001.3 r90 bottom
C161 "885012005056" 0402L 4444,3148 r180 top value=15pF
C162 "885012205037" 0402L 4377,3303 r90 top value=0.1uF
C163 "885012105012" 0402L 4377,3222 r270 top value=1uF
C164 "885012205037" 0402L 4211,2874.55 r0 bottom value=0.1uF
C165 "04023C103JAT2A" 0402L 4211,2909 r0 bottom value=0.01uF
C166 "C2012X7R1C335K125AB" 0805_HV 4577,3258 r270 top value=3.3uF
C167 "885012205037" 0402L 3268.3,2649.7 r180 bottom value=0.1uF
C168 "885012205037" 0402L 3211,2848 r180 bottom value=0.1uF
C169 "C2012X7R1C335K125AB" 0805L 3681,3245 r90 bottom value=3.3uF
C170 "885012105012" 0402L 3736,3227 r90 bottom value=1uF
C171 "885012205037" 0402L 3343,2911 r270 bottom value=0.1uF
C172 "885012105010" 0402L 1796,344 r270 top value=0.1uF
C173 "885012105010" 0402L 1642.24,252.65 r0 top value=0.1uF
C174 "885012105010" 0402L 1236.24,246.46 r0 top value=0.1uF
C175 "885012105010" 0402L 2935,1172 r180 bottom value=0.1uF
C176 "885012105010" 0402L 1589,452 r90 top value=0.1uF
C177 "885012105010" 0402L 844,2386 r270 bottom value=0.1uF
C178 "885012105010" 0402L 1996.28,676.44 r180 top value=0.1uF
C179 "885012105010" 0402L 3318,332 r0 top value=0.1uF
C180 "GRM155R61A106ME18D" FP-GRM155R61A106ME18D_0402-IPC_C 3305,283 r270 top value=10µF
C181 "885012106012" FP-885012106012_0603-IPC_C 3519,275 r90 top value=4.7µF
C182 "GRM155R61A106ME18D" FP-GRM155R61A106ME18D_0402-IPC_C 3318,367 r180 top value=10µF
C183 "885012205037" 0402L 2809,2902 r180 bottom value=0.1uF
C184 "885012205037" 0402L 1679,1913 r180 bottom value=0.1uF
C185 "885012205037" 0402L 1620,2012 r270 bottom value=0.1uF
C186 "885012205037" 0402L 1738,2051 r90 bottom value=0.1uF
C187 "GRM155R60J106ME47D" 0402L 1679,2034 r90 bottom value=10uF
C188 "885012107011" 0805_150 2780.13,1353.52 r90 bottom value=22uF
C189 "885012107011" 0805_150 2780.8,1494.54 r270 bottom value=22uF
C190 "885012104005" FP-885012104005_0201-IPC_C 2564,1147.01 r90 bottom value=100nF
C191_SOM-ETH1 "885012105012" 0402L 1582.13,1485.64 r180 bottom value=1uF (schematic designator C191)
C191_SOM-ETH2 "885012105012" 0402L 1581.13,1042.64 r180 bottom value=1uF (schematic designator C191)
C192 "885012105010" 0402L 1235.92,278.46 r0 top value=0.1uF
C193 "885012205086" FP-885012205086_0402-IPC_C 3095,465 r90 top value=100nF
C194 "04026D474KAT2A" 0402L 1236.24,214.46 r180 top value=0.47uF
C195 "04026D474KAT2A" 0402L 1438.24,214.46 r0 top value=0.47uF
C196 "885012205037" 0402L 2823,447 r0 top value=0.1uF
C197 "885012205037" 0402L 2617,449 r0 top value=0.1uF
C198 "885012104005" FP-885012104005_0201-IPC_C 2268,982 r0 bottom value=100nF
C199 "885012104005" FP-885012104005_0201-IPC_C 2589,1120.01 r90 bottom value=100nF
C200 "885012104005" FP-885012104005_0201-IPC_C 2550.99,1237 r180 bottom value=100nF
C201 "885012104005" FP-885012104005_0201-IPC_C 2445.51,929.5 r0 bottom value=100nF
C202 "885012104005" FP-885012104005_0201-IPC_C 2347.62,930.87 r180 bottom value=100nF
C203 "885012104005" FP-885012104005_0201-IPC_C 2574,956 r0 bottom value=100nF
C204 "885012104005" FP-885012104005_0201-IPC_C 2257,1096.99 r270 bottom value=100nF
C205 "885012104005" FP-885012104005_0201-IPC_C 2293.99,1212 r180 bottom value=100nF
C206 "C1608X6S1C335K080AC" 0603L 2423,990.56 r90 bottom value=3.3uF
C207 "885012105010" 0402L 1491.72,1172.43 r270 top value=0.1uF
C208 "885012105010" 0402L 1490.72,1248.43 r90 top value=0.1uF
C209 "885012104005" FP-885012104005_0201-IPC_C 2544.99,1211 r180 bottom value=100nF
C210 "885012104005" FP-885012104005_0201-IPC_C 2447.01,1212 r0 bottom value=100nF
C211 "885012205037" 0402L 3890,501 r0 top value=0.1uF
C212 "C1005X5R1A335K050BC" 0402L 2462.15,1373.48 r90 bottom value=3.3uF
C213 "885012104005" FP-885012104005_0201-IPC_C 2432.15,1363.48 r270 bottom value=100nF
C214 "C1005X5R1A335K050BC" 0402L 2360.15,1289.13 r180 bottom value=3.3uF
C215 "885012104005" FP-885012104005_0201-IPC_C 2384,1332.13 r270 bottom value=100nF
C216 "C1005X5R1A335K050BC" 0402L 2276.15,1264.17 r90 bottom value=3.3uF
C217 "885012104005" FP-885012104005_0201-IPC_C 2312.01,1252.03 r270 bottom value=100nF
C218 "885012205037" 0402L 3680.7,416.32 r180 top value=0.1uF
C219 "885012205037" 0402L 3757.39,416.32 r180 top value=0.1uF
D1 "150060VS75000" WL-SMCW_GREEN 3200,1783 r90 top value=Green
D2 "150060VS75000" WL-SMCW_GREEN 3087,1782 r90 top value=Green
D3 "150060VS75000" WL-SMCW_GREEN 3143,1783.07 r90 top value=Green
D4 "150060VS75000" WL-SMCW_GREEN 1064,3562 r90 top value=Green
D5 "150060VS75000" WL-SMCW_GREEN 969,3562 r90 top value=Green
D6 "150060VS75000" WL-SMCW_GREEN 1158,3562 r90 top value=Green
D7 "150066RG74000" FP-150066RG74000_0606-MFG 131.32,2853.69 r180 top
D8 "150066RG74000" FP-150066RG74000_0606-MFG 131.32,2971.69 r180 top
D10 "150060VS75000" WL-SMCW_GREEN 459.94,2904.99 r180 top value=Green
D11 "150060VS75000" WL-SMCW_GREEN 459.94,2855.57 r180 top value=Green
D12 "150060VS75000" WL-SMCW_GREEN 459.94,2806.16 r180 top value=Green
D13 "150060VS75000" WL-SMCW_GREEN 459.94,2756.74 r180 top value=Green
D14 "150060VS75000" WL-SMCW_GREEN 459.94,2707.32 r180 top value=Green
D15 "150060VS75000" WL-SMCW_GREEN 459.94,2657.9 r180 top value=Green
D16 "150060VS75000" WL-SMCW_GREEN 459.94,2608.48 r180 top value=Green
D17 "150060VS75000" WL-SMCW_GREEN 459.94,2559.06 r180 top value=Green
D18 "SMBJ6.5CA" SMB-Bi 2039.32,3463 r270 top value=6.5V
D19 "150060RS75000" WL-SMCW_RED 2150.28,2931 r270 top value=Red
D20 "150060VS75000" WL-SMCW_GREEN 4271,3025 r180 top value=Green
D21 "150060RS75000" WL-SMCW_RED 4271,3092 r180 top value=Red
D22 "SMBJ6.5CA" SMB-Bi 4852.43,3518.77 r270 top value=6.5V
D23 "150060VS75000" WL-SMCW_GREEN 133.5,2743 r180 top value=Green
D24 "150060VS75000" WL-SMCW_GREEN 1882,220 r270 top value=Green
F1 "0454002.MR" SloBlo452 663,3553 r180 top
FID1 "Fiducial" Fiducial10-20 660,3202 r0 top
FID2 "Fiducial" Fiducial10-20 4862,3286 r0 top
FID3 "Fiducial" Fiducial10-20 4802,347 r0 top
FID4 "Fiducial" Fiducial10-20 4862,3286 r180 bottom
FID5 "Fiducial" Fiducial10-20 4802,347 r180 bottom
FID6 "Fiducial" Fiducial10-20 660,3202 r180 bottom
H1 "NY PMS 440 0025 PH" "NY PMS 440 0025 PH" 4849,2010 r0 top
H2 "NY PMS 440 0025 PH" "NY PMS 440 0025 PH" 4853,793 r0 top
J1 "PJ-102AH" CUI_PJ-102AH 429.11,3276 r270 top
J2 "7498011211" FP-7498011211_RJ45MAG-MFG 434.59,1860 r270 top
J3 "7498011211" FP-7498011211_RJ45MAG-MFG 434.59,620 r270 top
J4 "7466313R" FP-7466313R_SMT_REDCUBE_7MM00_4MM33-MFG 123,1240 r90 top
J5 "61300211121" WURTH_61300211121 2097,387 r0 top
J6 "693071010811" Molex_693071010811 3385,333 r180 bottom
J7 "61300621121" Wurth_61300621121 4180,154 r90 top
J8 "61300621121" Wurth_61300621121 3860,154 r90 top
J9 "61301021121" WURTH_61301021121 4600,154 r0 top
J10 "61301221121" FP-61301221121_HDR12-MFG 2778,154 r0 top
J11 "QSH-030-01-L-D-A" Samtec_QSH-030-01-X-D-A 4850,1401.48 r0 bottom
J12 "61300311121" WURTH_61300311121 4632,2956 r0 top
J13 "629105150921" FP-629105150921_CONN_PTH_USB_8MM0_5MM6-MFG 2960,3592 r180 top
J14 "632723300011" FP-632723300011_CONN_USB_8MM74_11MM20-MFG 2378,3450.1 r180 top
J15 "629105150921" FP-629105150921_CONN_PTH_USB_8MM0_5MM6-MFG 4558,3591 r180 top
J16 "FTR-110-51-S-D-06" Samtec_FTR-110-51-x-D-06 3815.43,3463.78 r270 top
J17 "61300211121" WURTH_61300211121 3425,3458 r90 top
J18 "61300211121" WURTH_61300211121 2999,346 r180 top
J20 "61300211121" WURTH_61300211121 2682,3337 r270 top
L1 "74479262147" WE-PMCI_0603LP 3160.13,1464.95 r0 top value=470nH
L2 "74479262147" WE-PMCI_0603LP 2837.13,1370.36 r270 top value=470nH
